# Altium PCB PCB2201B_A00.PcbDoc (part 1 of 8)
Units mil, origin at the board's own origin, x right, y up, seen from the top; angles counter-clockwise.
Board outline 4523.63 x 2358.23 mil, 6 copper layers (Top Layer, Signal Layer 2, Signal Layer 3, Signal Layer 4, Signal Layer 5, Bottom Layer), stack 61.221 mil thick; 383 components, 308 nets, 1386 pads, 1147 vias.
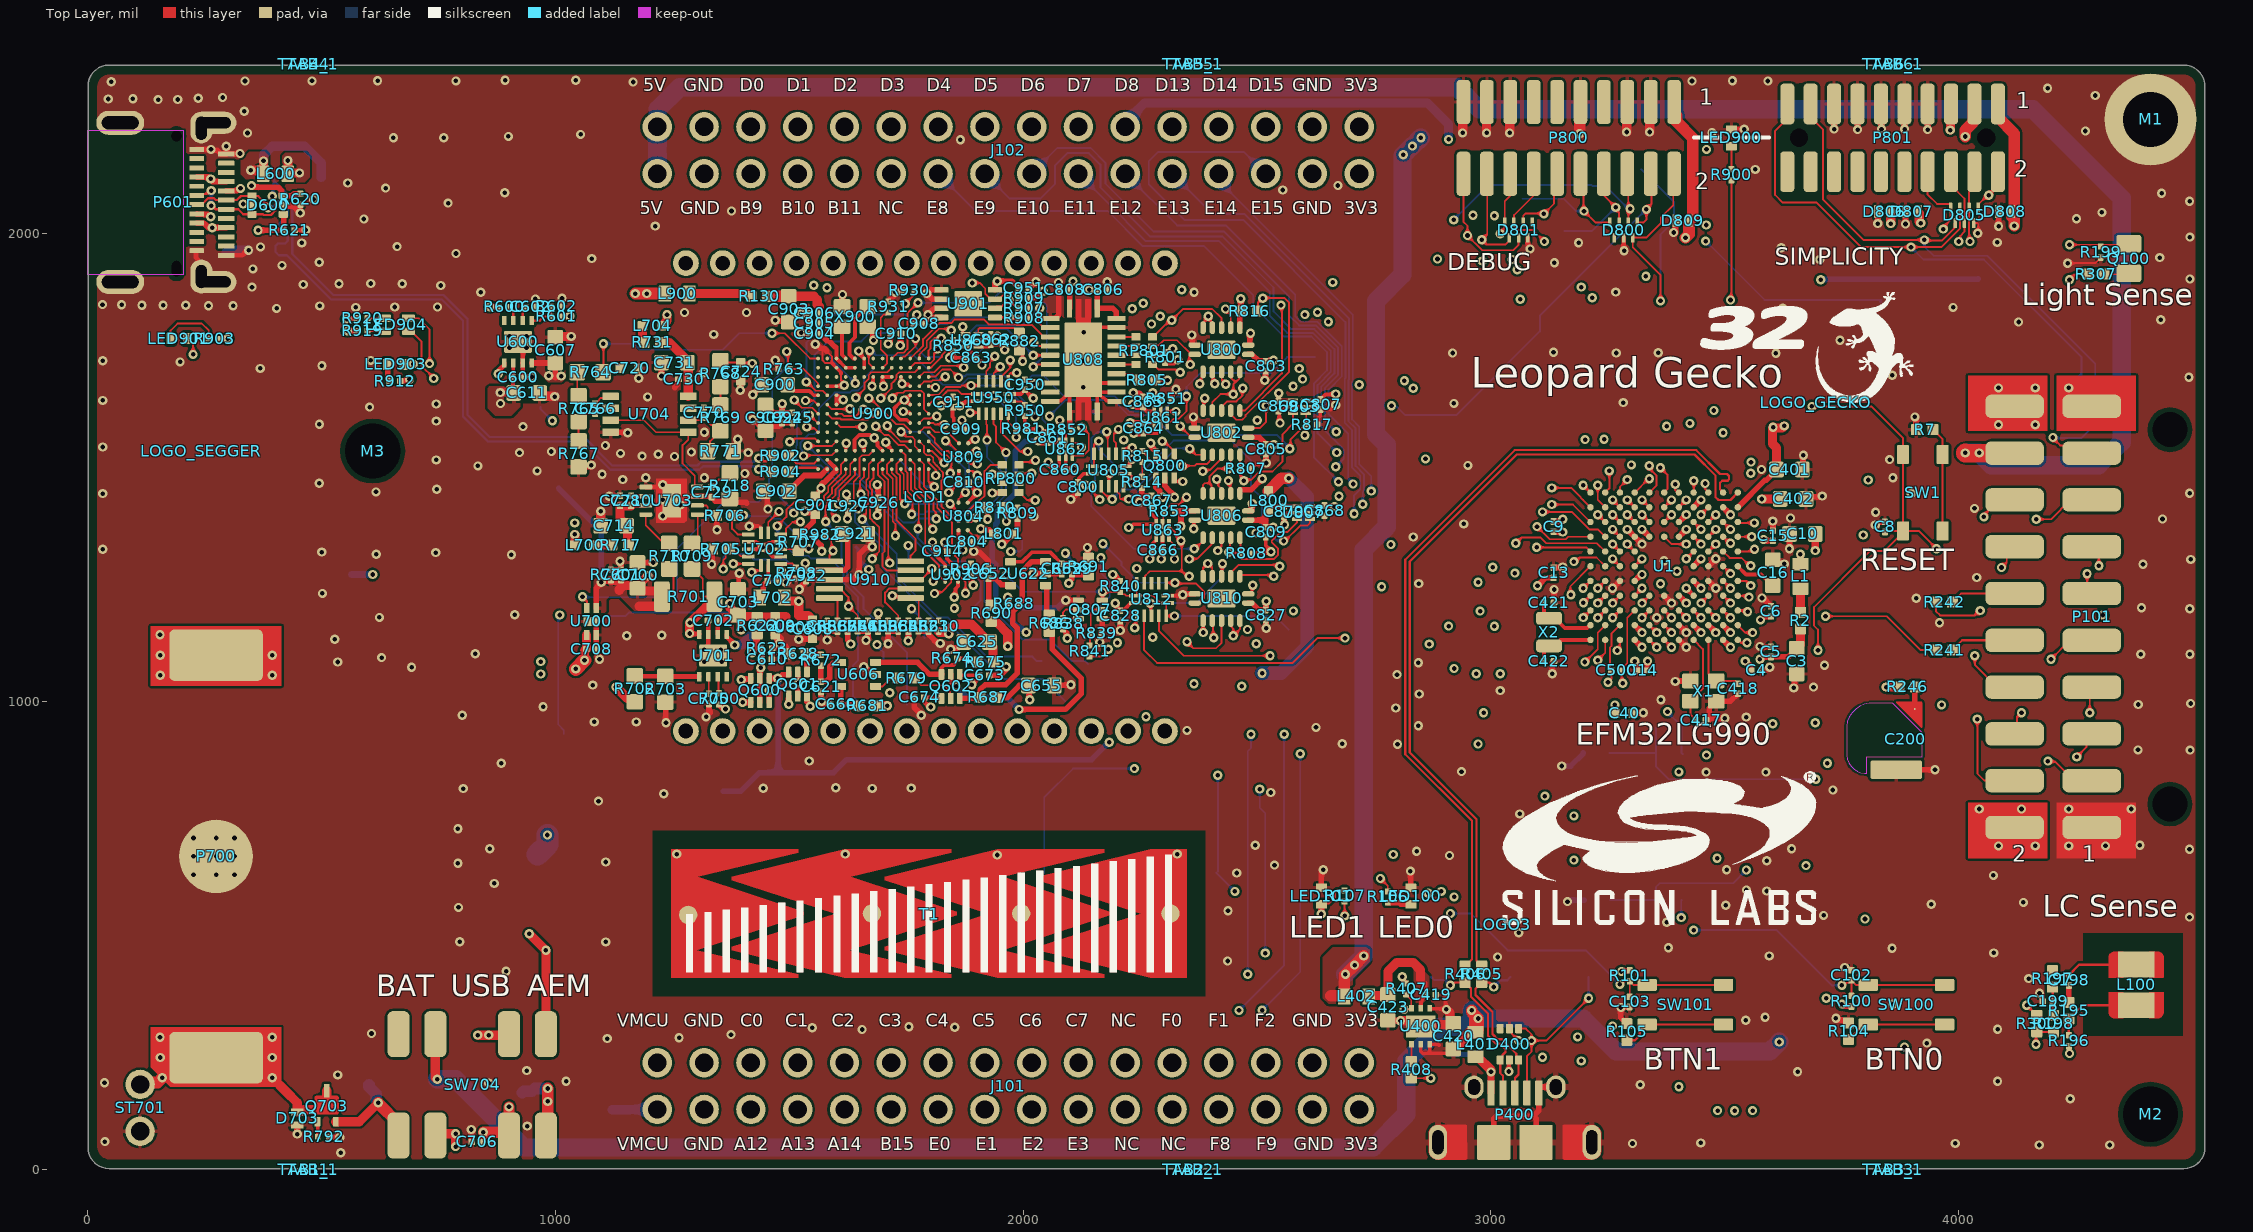
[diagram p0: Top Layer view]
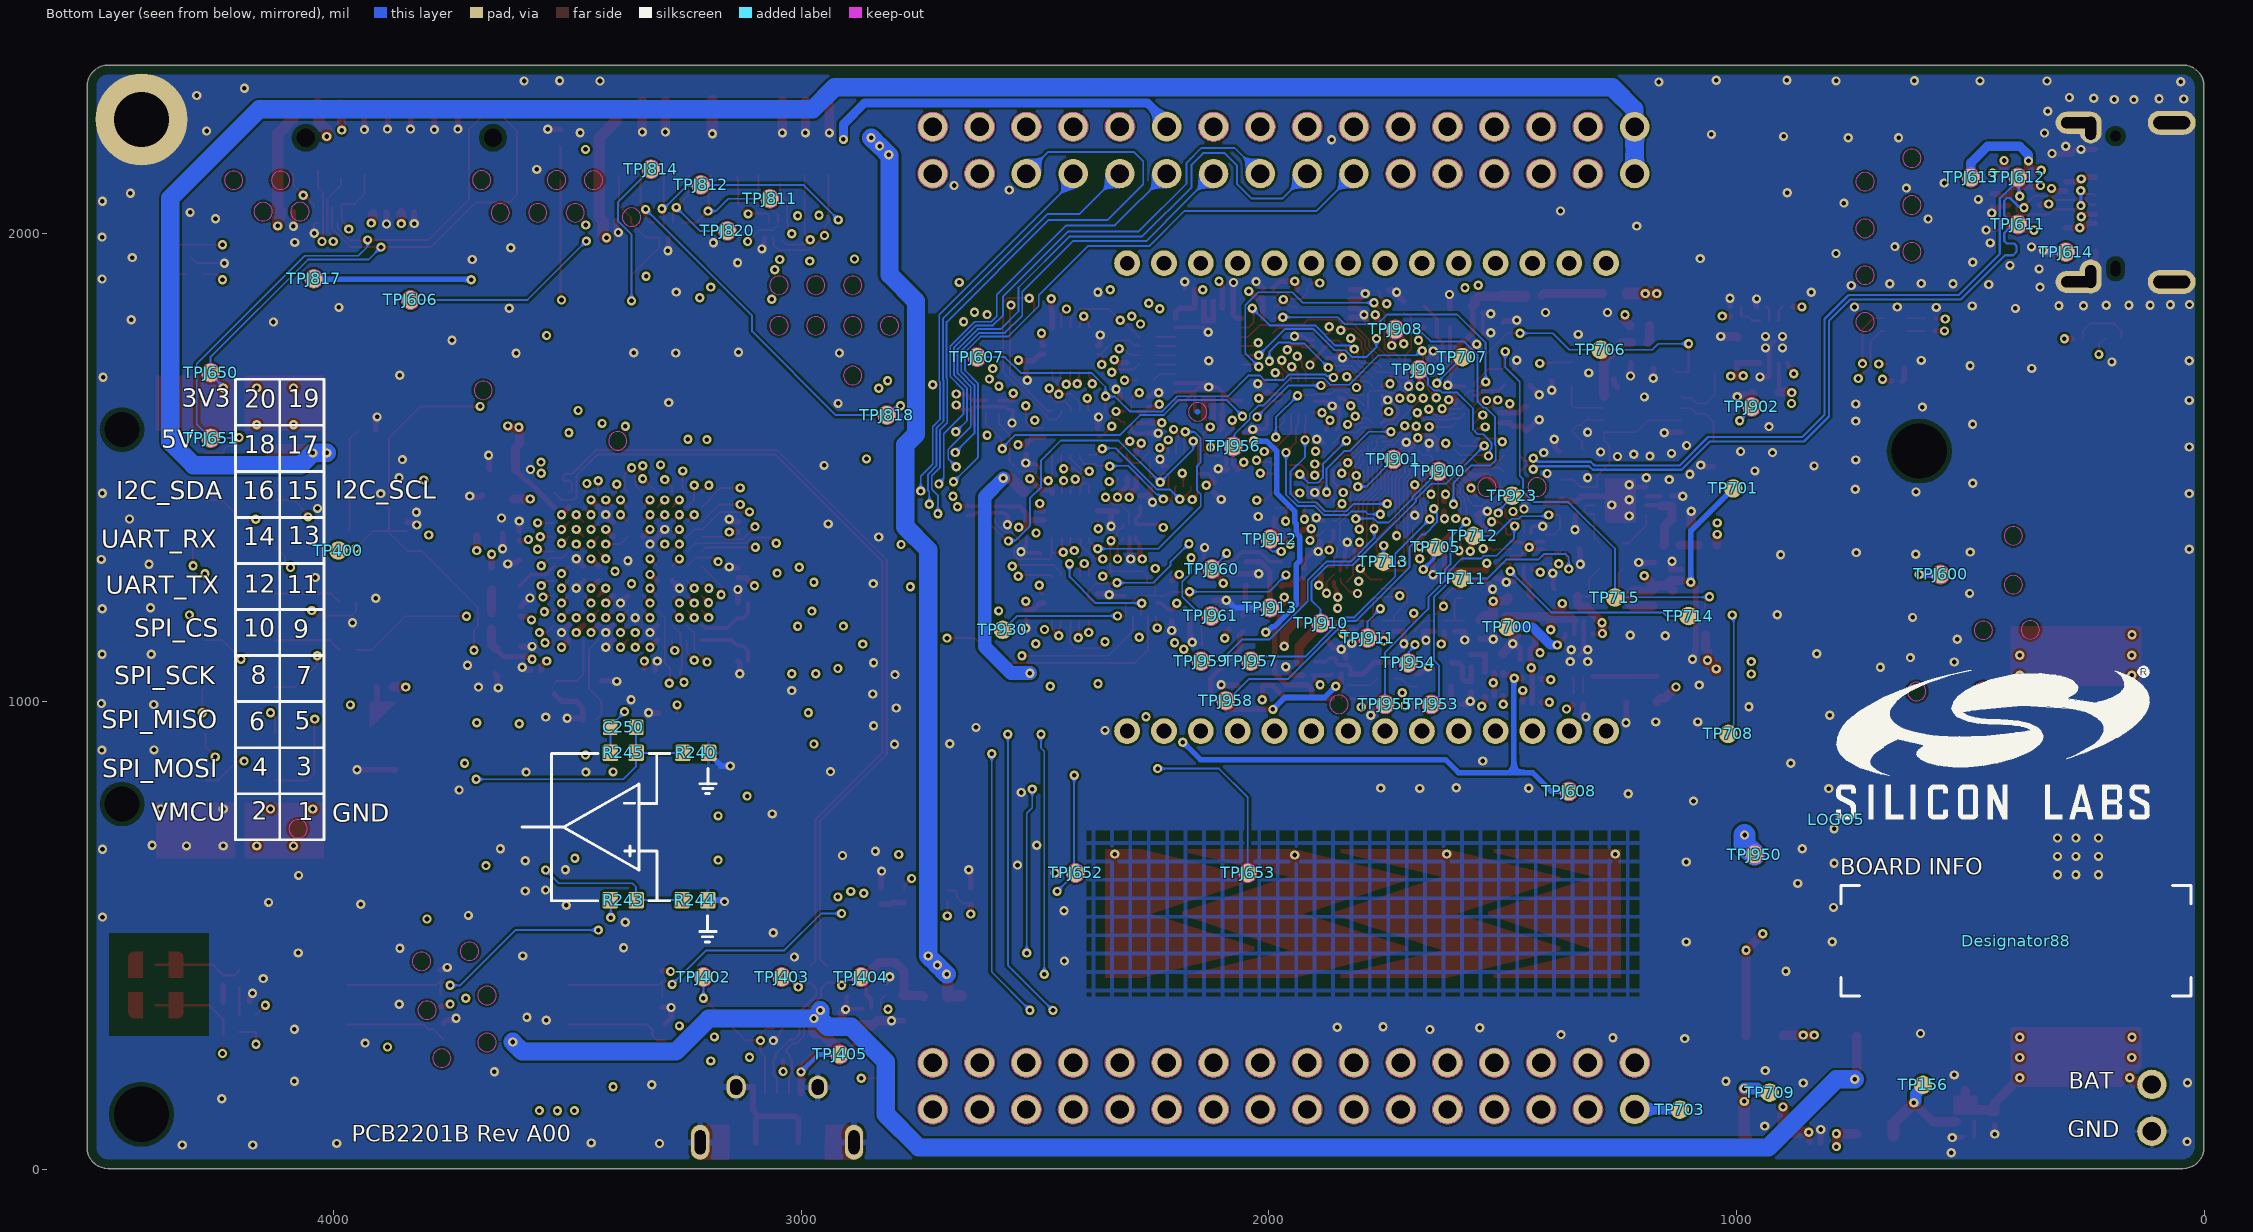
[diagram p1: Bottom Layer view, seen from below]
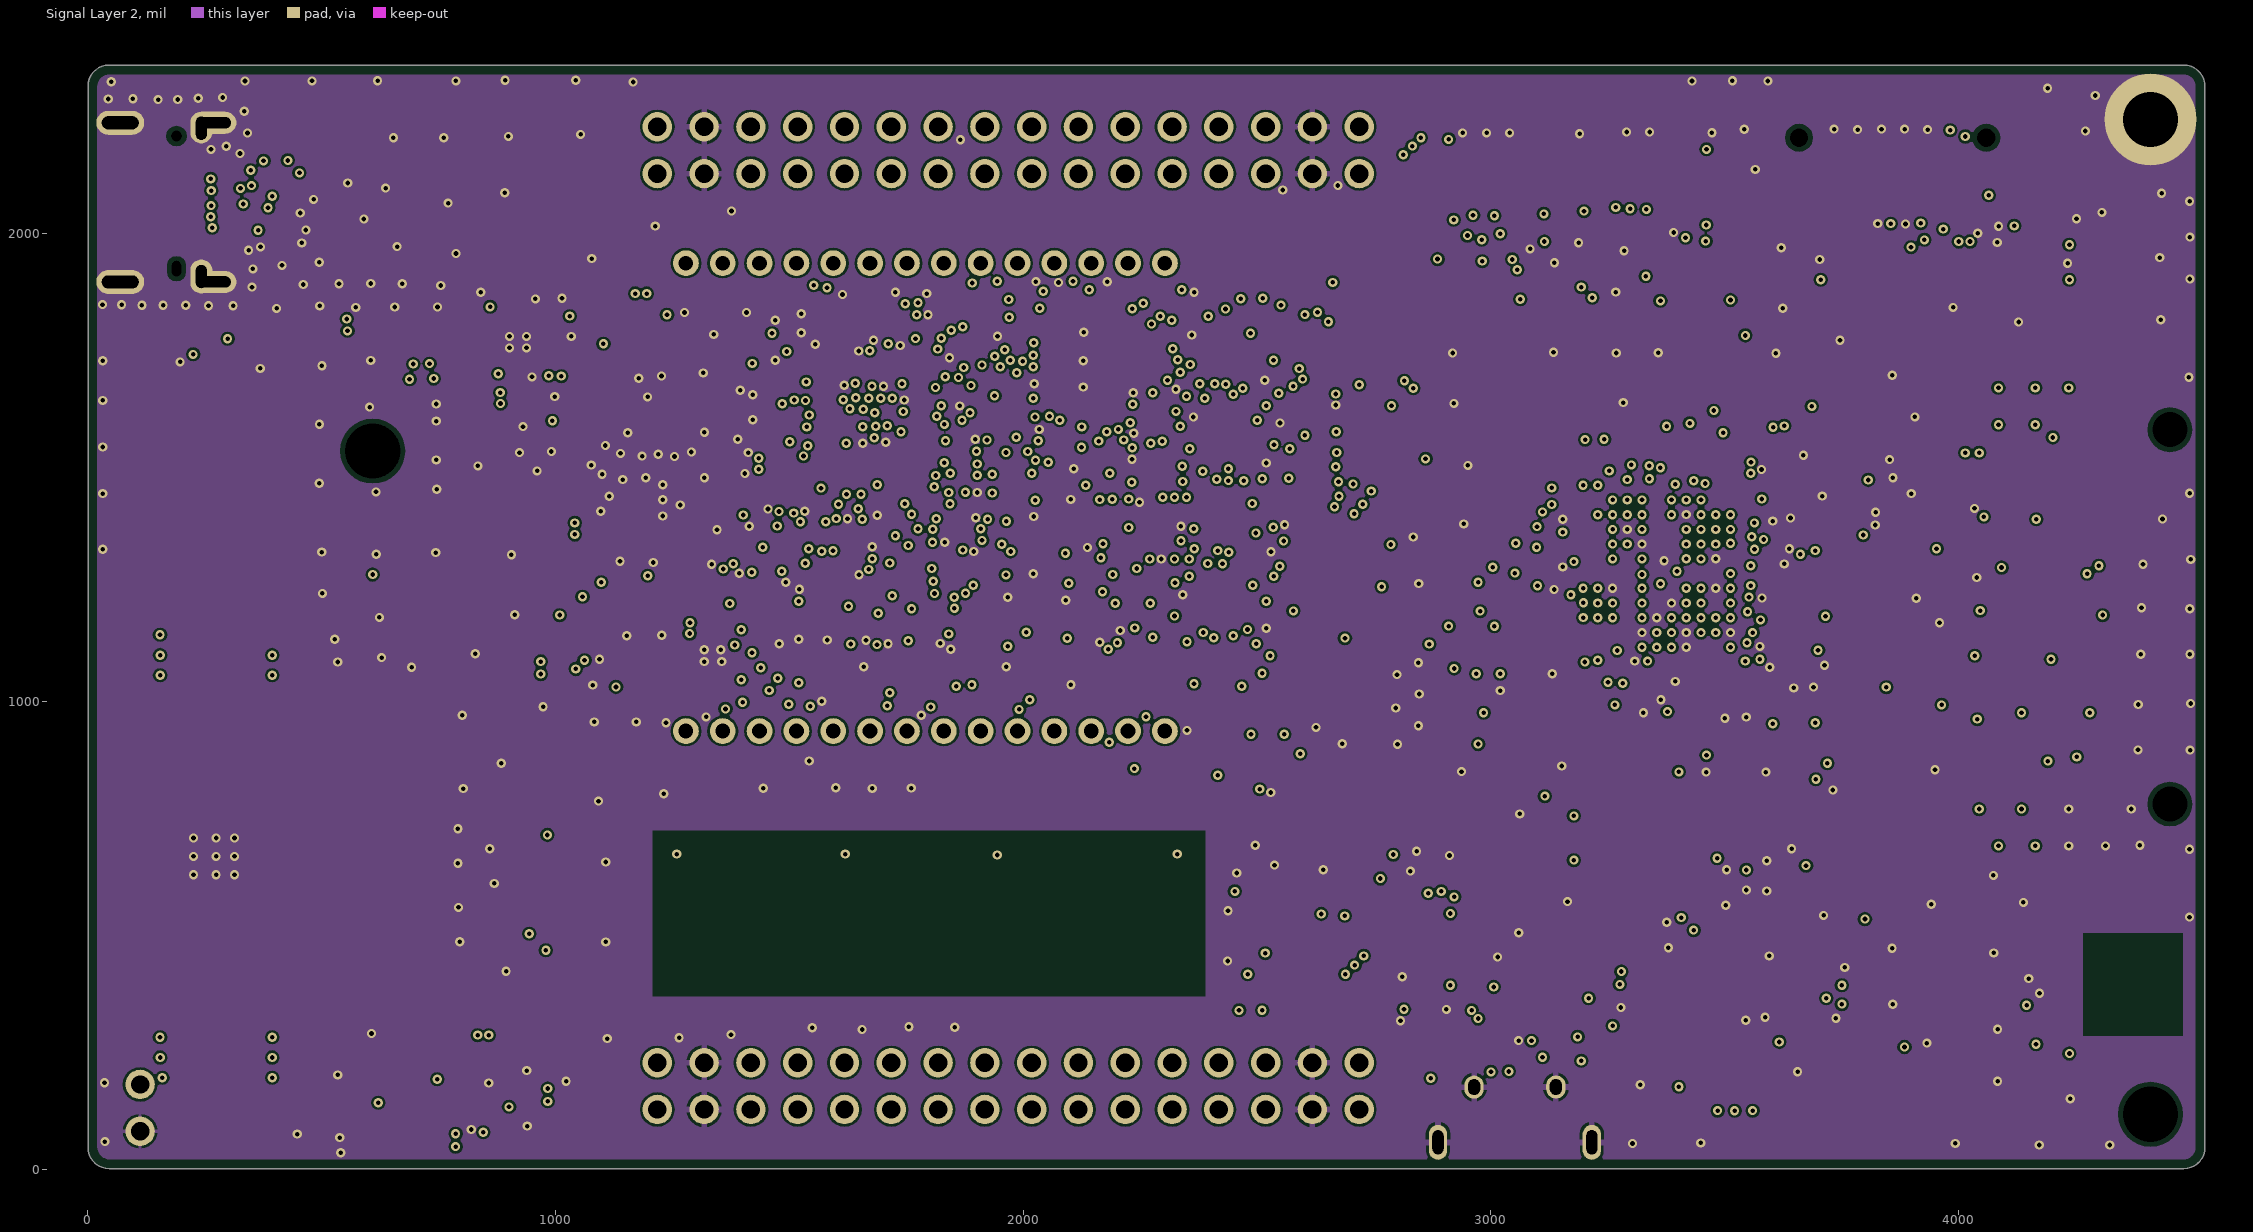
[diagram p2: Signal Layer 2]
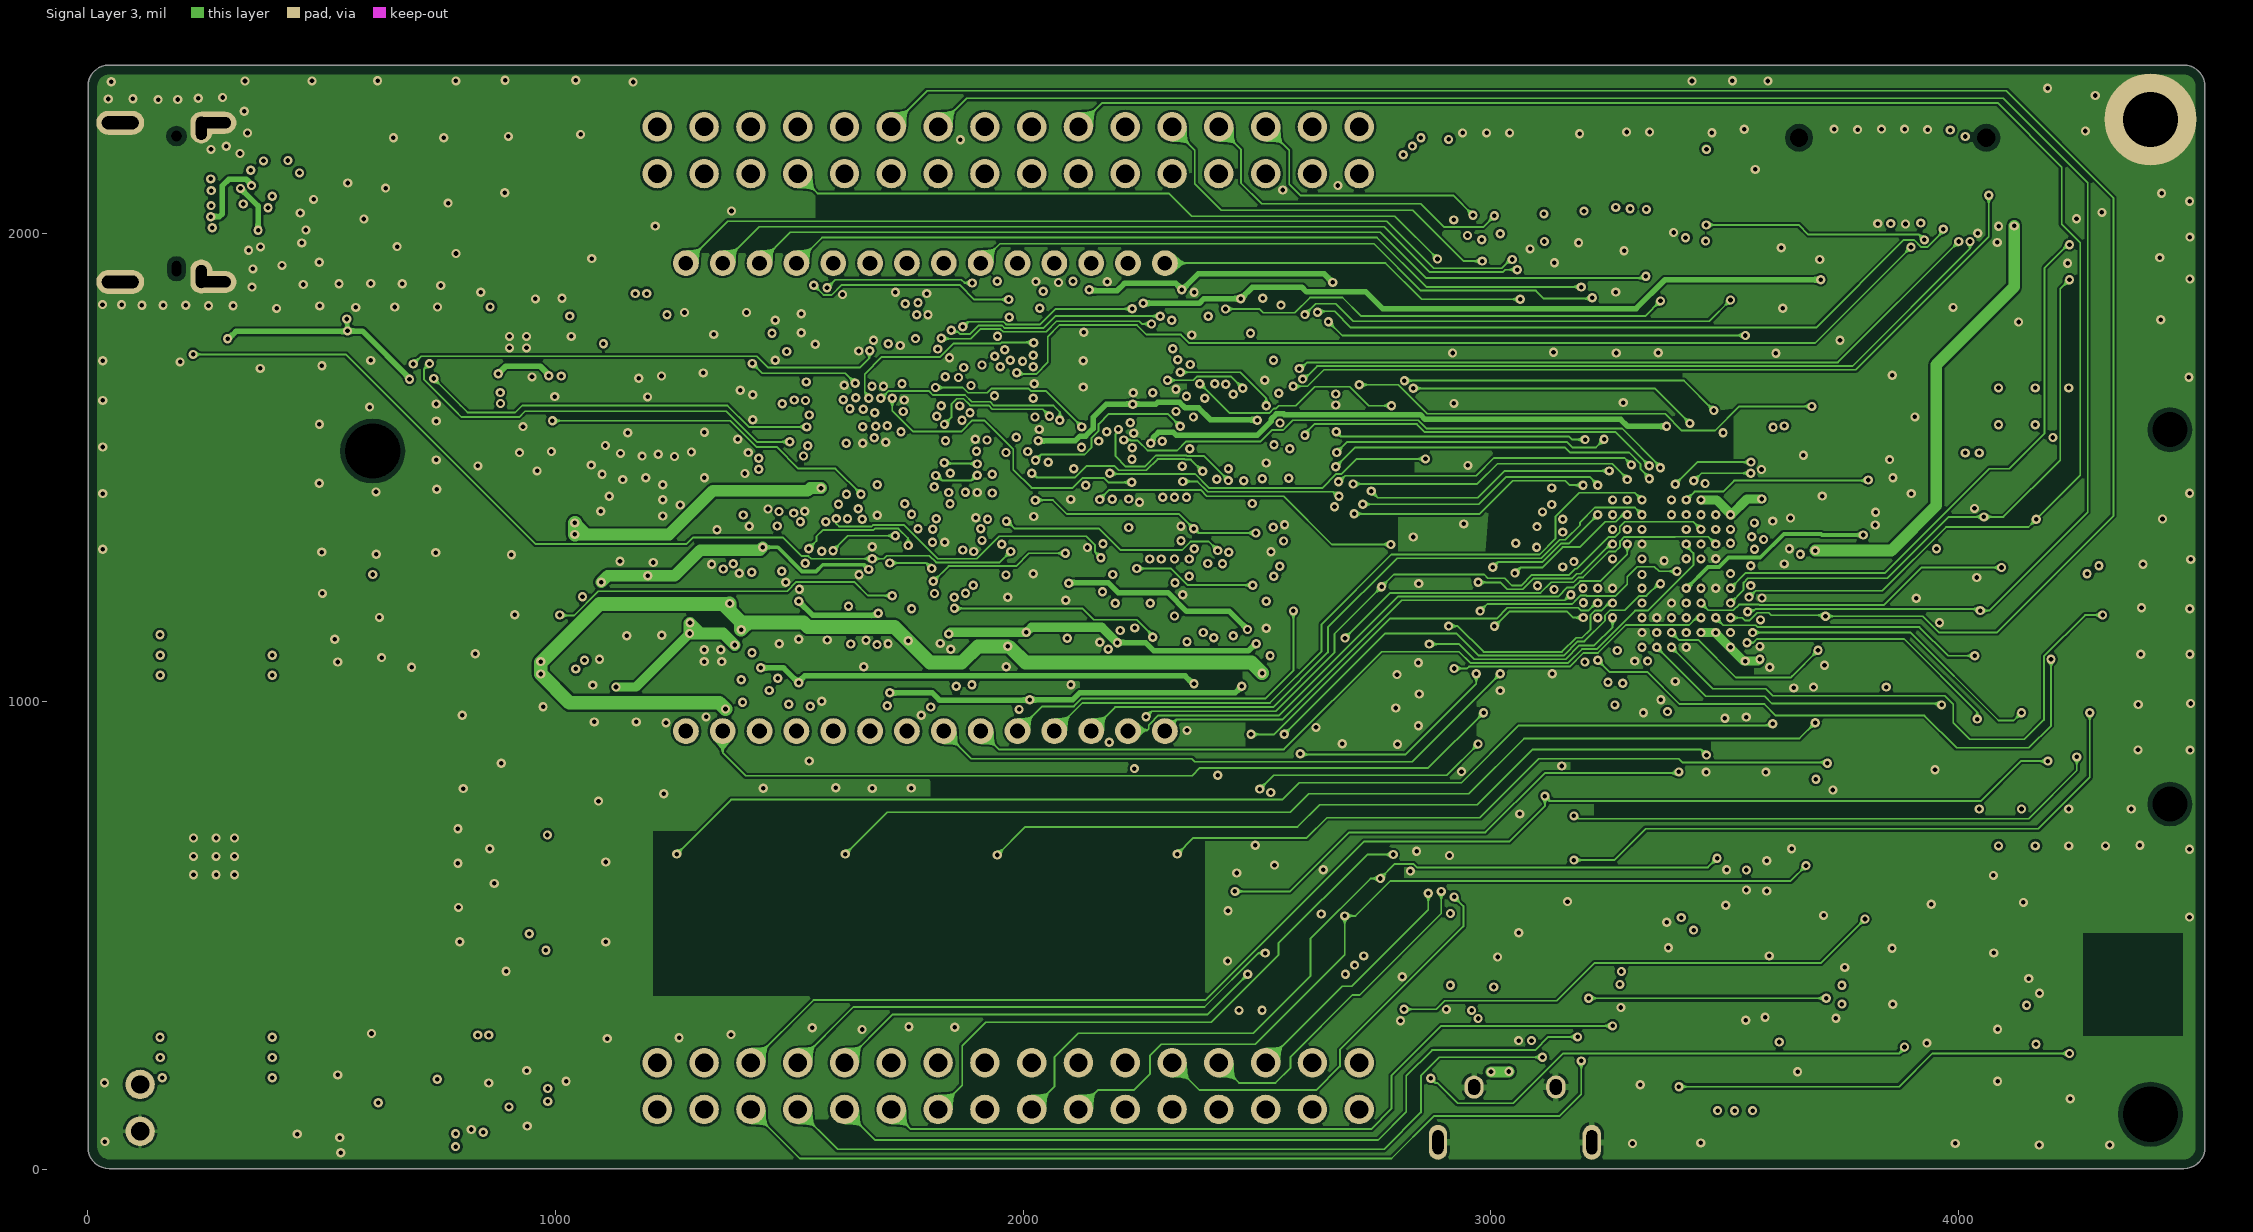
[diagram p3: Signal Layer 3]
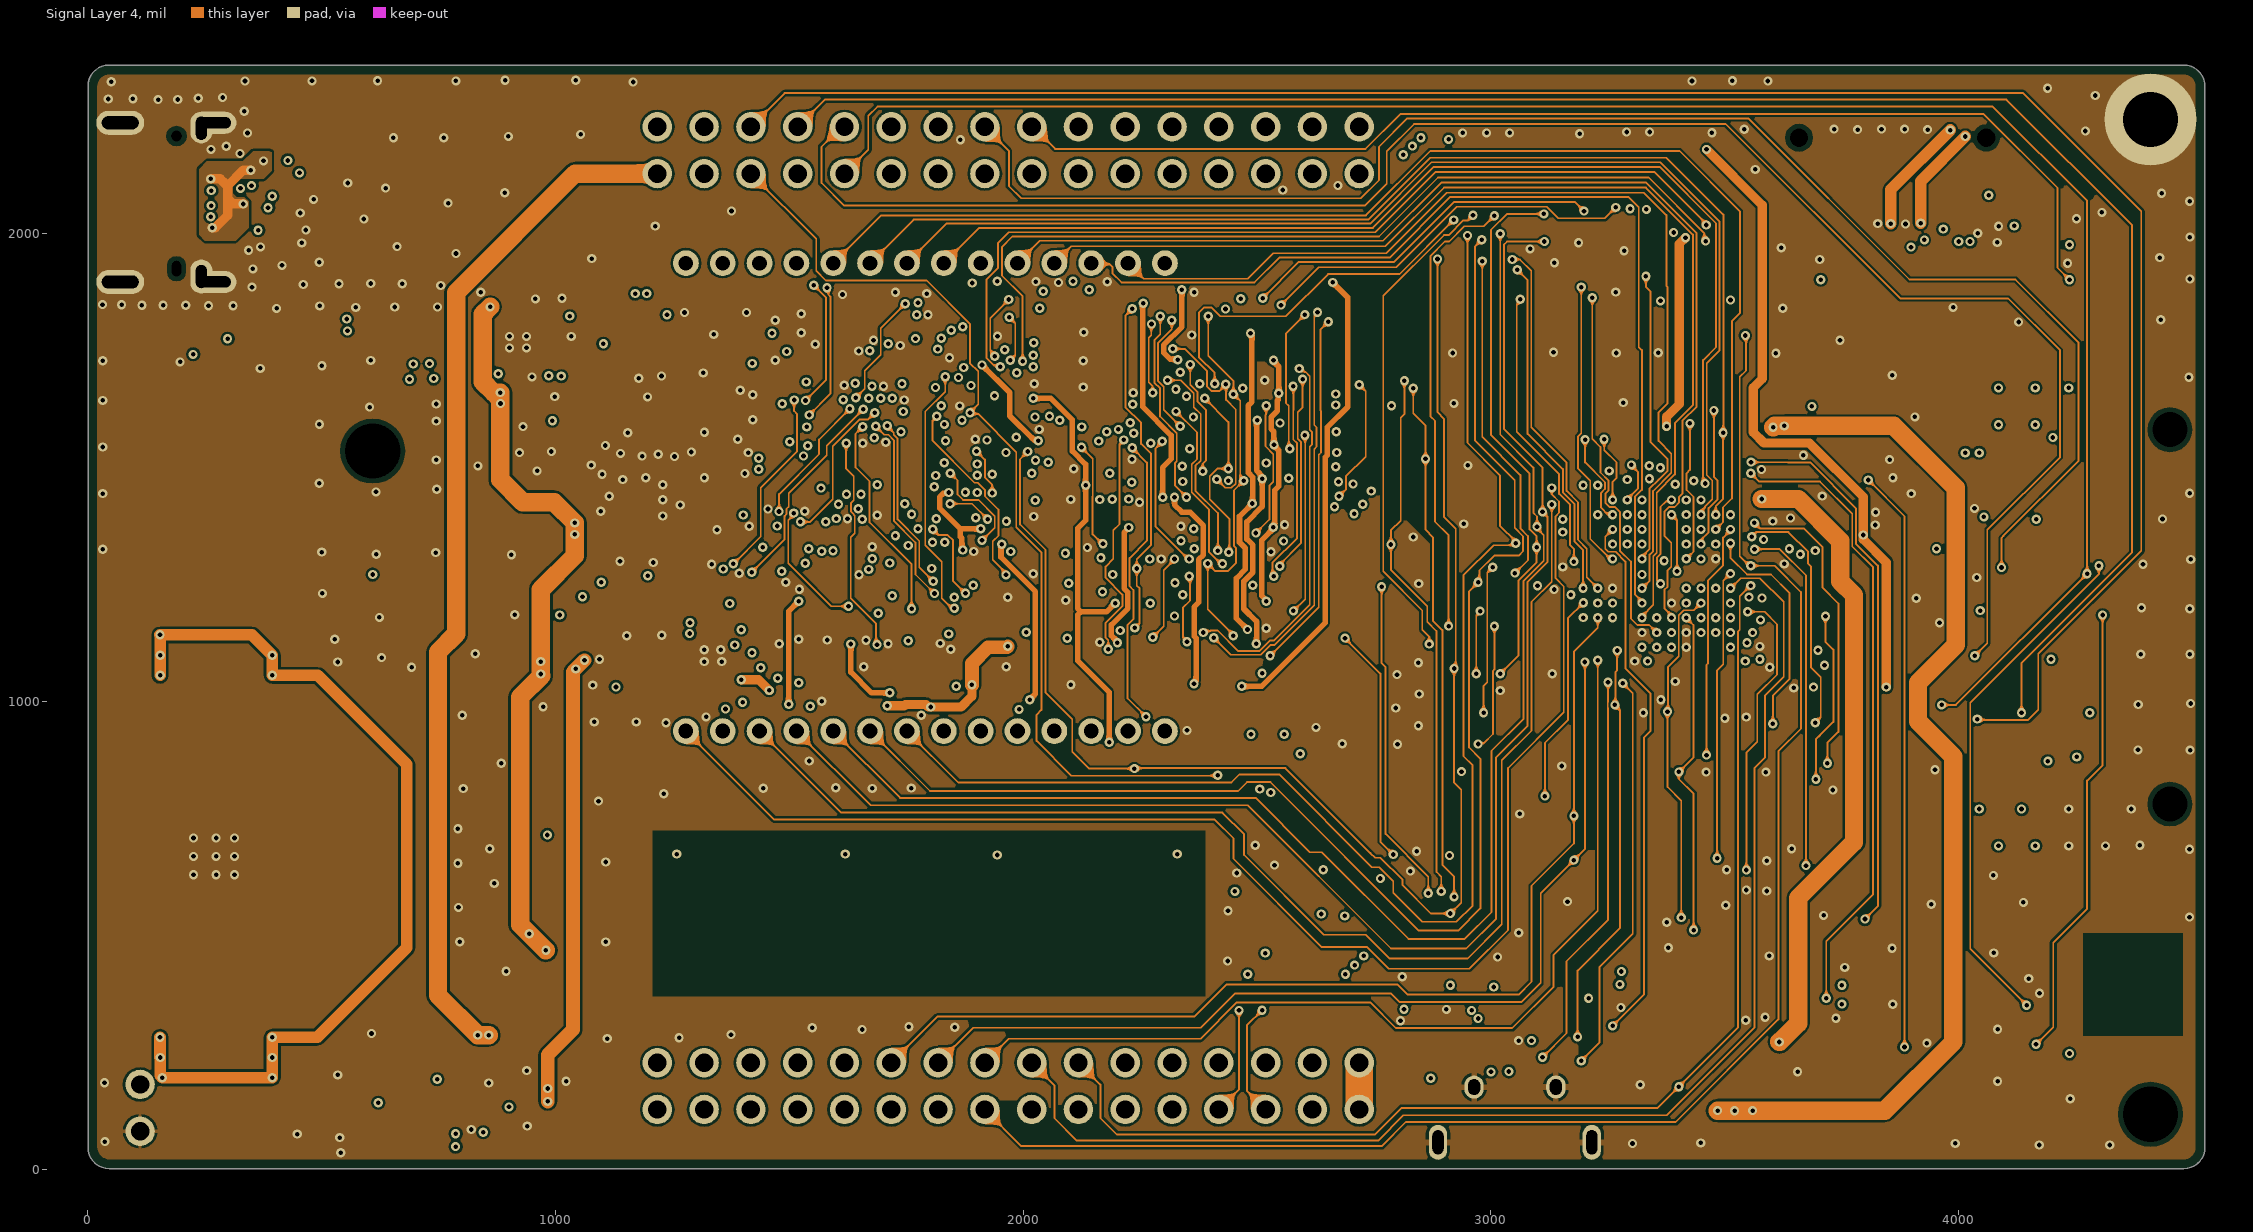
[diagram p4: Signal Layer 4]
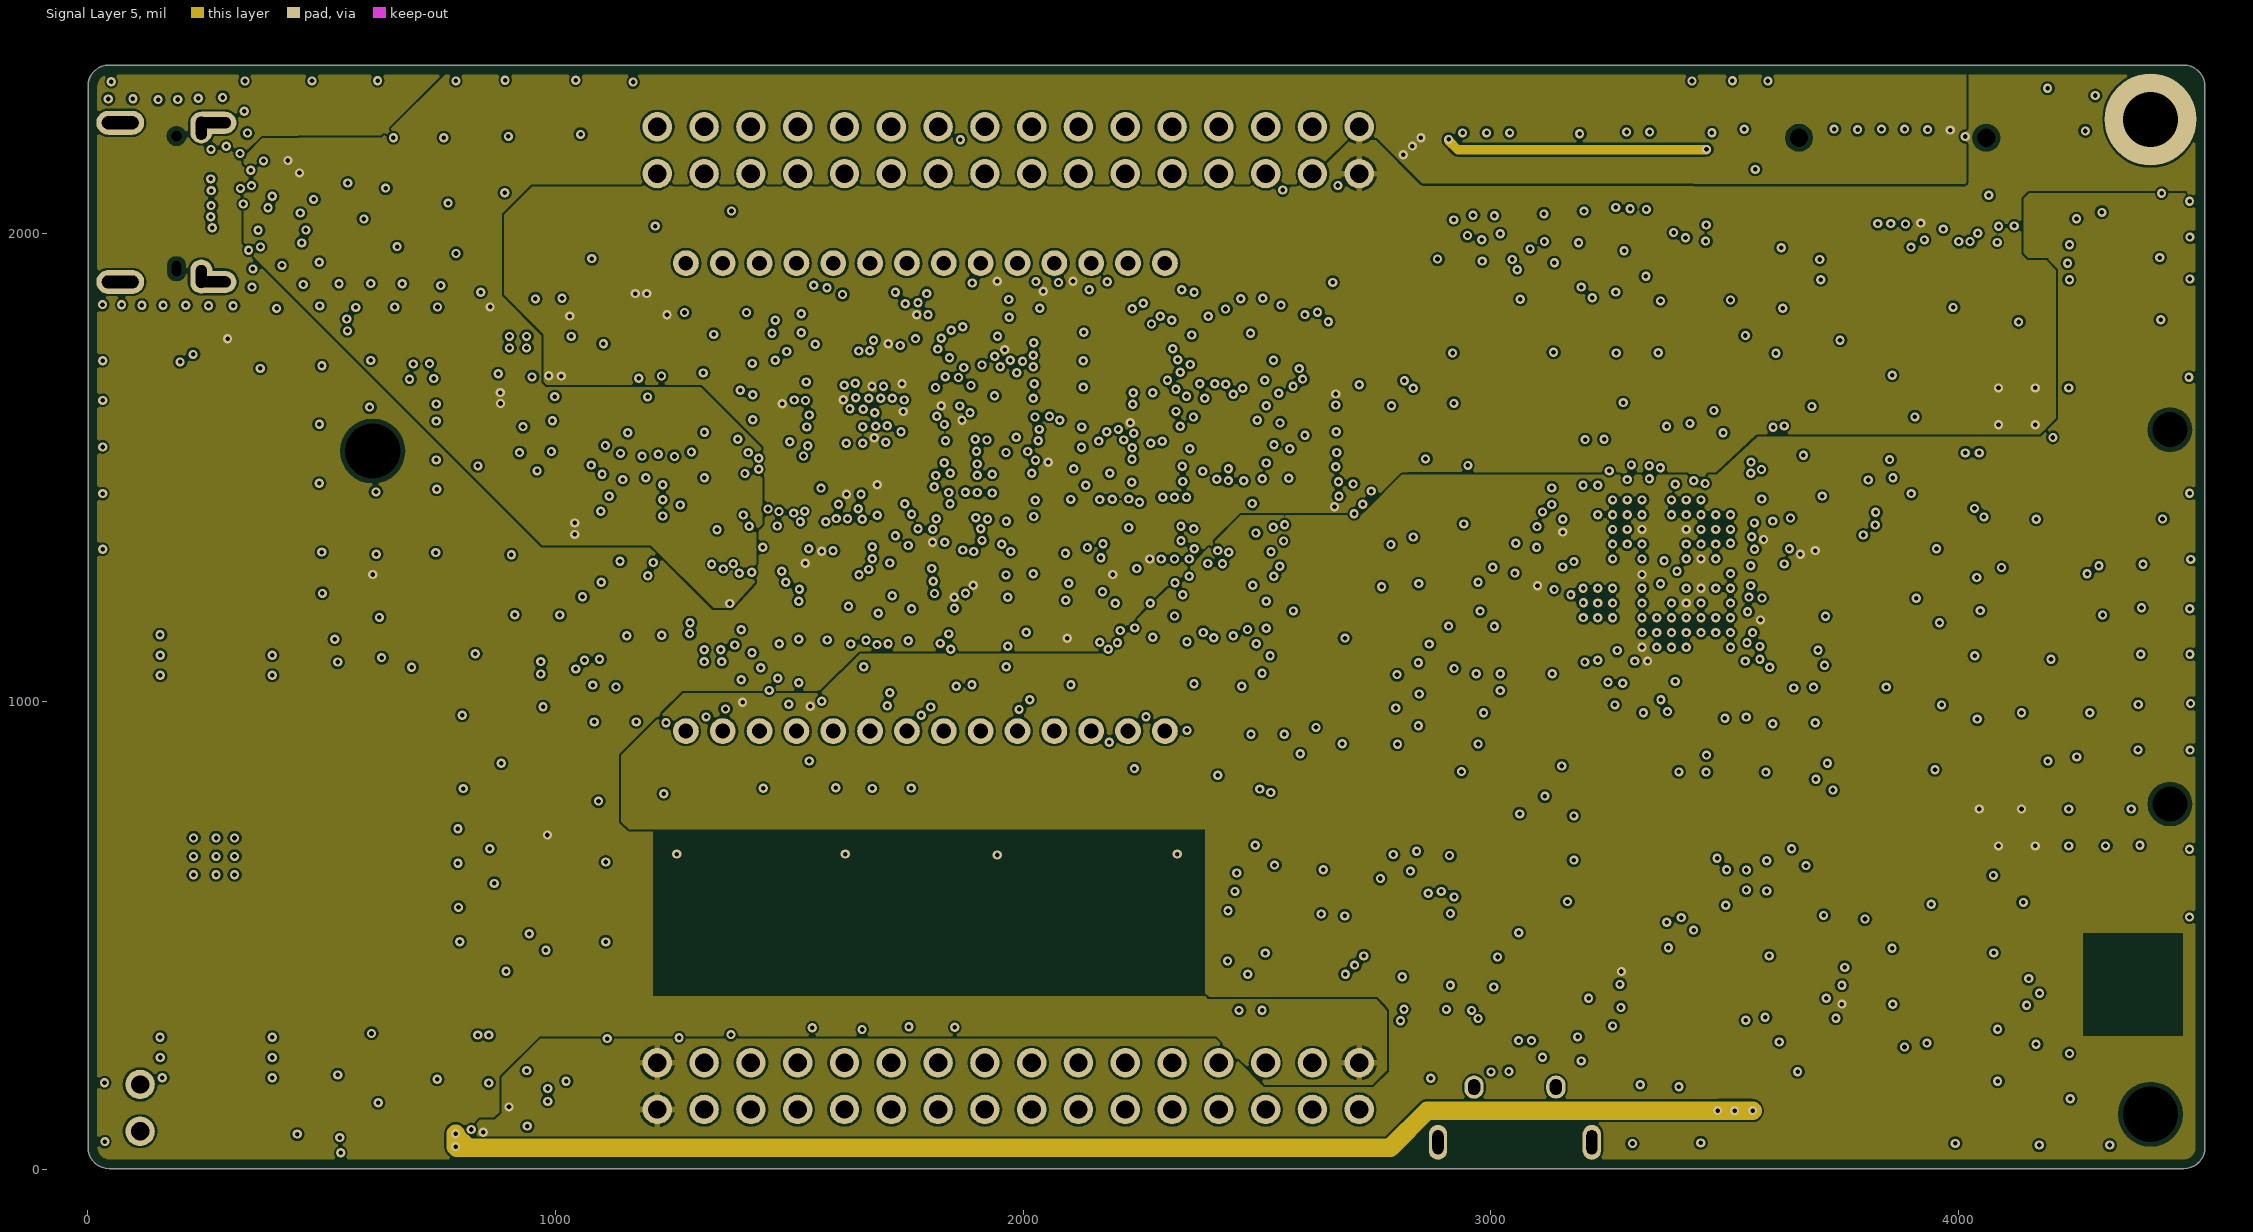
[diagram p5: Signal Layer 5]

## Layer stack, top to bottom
Top Solder: solder mask 1.9685, Solder Resist, Dk 3.5
Top Layer: signal copper 1.378
Dielectric 1: prepreg 3.937, FR-4, Dk 4.2
Signal Layer 2: signal copper 1.378
Dielectric 2: core 18.1102, FR-4, Dk 4.2
Signal Layer 3: signal copper 1.378
Dielectric 3: prepreg 8.8583, FR-4, Dk 4.2
Signal Layer 4: signal copper 1.378
Dielectric 4: core 18.1102, FR-4, Dk 4.2
Signal Layer 5: signal copper 1.378
Dielectric 5: prepreg 3.937, FR-4, Dk 4.2
Bottom Layer: signal copper 1.378
Bottom Solder: solder mask 1.9685, Solder Resist, Dk 3.5

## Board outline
8.03,24.6 4.77,31.78 2.66,39.35 1.98,47.28 1.98,2315.31 2.66,2323.16 4.67,2330.72 8.02,2337.8 12.52,2344.22 17.98,2349.68 24.4,2354.18 31.48,2357.53 39.04,2359.54 46.98,2360.22 4480.22,2360.22 4488.16,2359.54 4495.82,2357.53 4502.91,2354.18 4509.42,2349.68 4514.97,2344.03 4519.48,2337.6 4522.83,2330.42 4524.84,2322.85 4525.62,2315 ccw(c4527.6,2315) 4525.62,2315 4525.62,46.98 4524.94,39.05 4522.83,31.48 4519.57,24.39 4515.08,17.99 4509.53,12.53 4503.1,8.02 4496.01,4.67 4488.55,2.66 4480.62,1.98 47.28,1.98 39.35,2.66 31.78,4.77 24.6,8.03 18.19,12.62 12.62,18.19

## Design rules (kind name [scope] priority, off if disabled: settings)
BoardOutlineClearance [Not InPadClass('Outside_Board')] p1: gap=19.68 ignorepadtopadclearanceinfootprint=FALSE except(10.24: Arc-CutoutEdge Track-CutoutEdge SMDPad-CutoutEdge THPad-CutoutEdge Via-CutoutEdge Fill-CutoutEdge Poly-CutoutEdge Region-CutoutEdge Text-CutoutEdge; 15.75: THPad-OutlineEdge Region-OutlineEdge Region-CavityEdge Region-SplitBarrior Region-SplitContinuation)
Clearance Clearance_NPL [(ObjectKind = 'Pad') And (Layer = 'MultiLayer') And (PadIsPlated = 'False')] p1: gap=9.84 ignorepadtopadclearanceinfootprint=FALSE
Clearance USB [InNetClass('USB')] p2: gap=5.67 ignorepadtopadclearanceinfootprint=FALSE
Clearance "Clearance_ThermalPad to Via" [IsPad and InNet('GND') vs IsVia] p3 off: gap=-39.37 ignorepadtopadclearanceinfootprint=FALSE except(0: Arc-Hole Track-Hole SMDPad-Hole THPad-Hole Via-Hole Fill-Hole Poly-Hole Region-Hole Text-Hole)
Clearance Clearance_Polygon_USB [InPolygon vs InNetClass('USB')] p4: gap=9.84 ignorepadtopadclearanceinfootprint=FALSE except(0: Arc-Hole Track-Hole SMDPad-Hole THPad-Hole Via-Hole Fill-Hole Poly-Hole Region-Hole Text-Hole)
Clearance Clearance_Polygon [InPolygon] p5: gap=4.92 ignorepadtopadclearanceinfootprint=FALSE
Clearance Clearance_Via_Track [IsVia vs IsTrack] p6: gap=3.5 ignorepadtopadclearanceinfootprint=FALSE except(0: Arc-Hole Track-Hole SMDPad-Hole THPad-Hole Via-Hole Fill-Hole Poly-Hole Region-Hole Text-Hole)
Clearance Clearance_Via_Pad [IsVia vs IsPad] p7 off: gap=1 ignorepadtopadclearanceinfootprint=FALSE except(0: Arc-Hole Track-Hole SMDPad-Hole THPad-Hole Via-Hole Fill-Hole Poly-Hole Region-Hole Text-Hole)
Clearance USB_LINE [InNet('DBGMCU_USB_DM') vs InNet('DBGMCU_USB_DP')] p8: gap=4 ignorepadtopadclearanceinfootprint=FALSE
Clearance Pad2PAD [IsPad vs IsPad] p9: gap=3.94 ignorepadtopadclearanceinfootprint=TRUE except(0: Arc-Hole Track-Hole SMDPad-Hole THPad-Hole Via-Hole Fill-Hole Poly-Hole Region-Hole Text-Hole)
Clearance [All] p10: gap=3.94 ignorepadtopadclearanceinfootprint=FALSE
ComponentClearance [All] p1: gap=3.94 collisioncheckmode=3 verticalgap=10 showdistances=TRUE
DiffPairsRouting [InAnyDifferentialPair] p1: maxlimit=4.72 minlimit=4.72 mostfreqgap=4.72 toplayer_minwidth=4.72 toplayer_maxwidth=4.72 toplayer_prefwidth=4.72 midlayer1_minwidth=4.72 midlayer1_maxwidth=4.72 midlayer1_prefwidth=4.72 midlayer2_minwidth=4.72 midlayer2_maxwidth=4.72 midlayer2_prefwidth=4.72 midlayer3_minwidth=4.72 midlayer3_maxwidth=4.72 midlayer3_prefwidth=4.72 midlayer5_minwidth=4.72 midlayer5_maxwidth=4.72 midlayer5_prefwidth=4.72 bottomlayer_minwidth=4.72 bottomlayer_maxwidth=4.72 bottomlayer_prefwidth=4.72 maxuncoupledlength=500
HoleSize [All] p1: absolutevalues=TRUE maxlimit=393.7 minlimit=3.94 maxpercent=80.000 minpercent=20.000
HoleToHoleClearance [InComponent('P601') vs InComponent('P601')] p1: gap=0 allowstackedmicrovias=TRUE
HoleToHoleClearance HoleToHoleClearance_U1toVIA_1 [InComponent ('U1') vs IsVia] p2: gap=0 allowstackedmicrovias=TRUE
HoleToHoleClearance HoleToHoleClearance_general [All] p3: gap=10 allowstackedmicrovias=TRUE
MinimumSolderMaskSliver [All] p1: minsoldermaskwidth=4
ParallelSegment [InNet('MCU_PC11') OR InNet('MCU_PC10') OR InNet('MCU_PC9') OR InNet('MCU_PC8')] p1: limit=472.44 gap=19.29
PolygonConnect [InComponent('J101') or InComponent('J102') vs InNet('GND')and not OnLayer('Signal Layer 2')] p1: connectstyle=NoConnect reliefconductorwidth=10 reliefentries=4 polygonreliefangle="90 Angle" airgapwidth=4.92
PolygonConnect PolygonConnect_TH [InComponent('J101') Or InComponent('J102') Or InComponent('ST1') Or InComponent('P400') Or InComponent('J710')] p2: connectstyle=Relief reliefconductorwidth=13 reliefentries=4 polygonreliefangle="90 Angle" airgapwidth=6
PolygonConnect PolygonConnect_P601 [InComponent('P601')] p3: connectstyle=Direct reliefconductorwidth=13 reliefentries=4 polygonreliefangle="90 Angle" airgapwidth=6
PolygonConnect PolygonConnect_M1 [InComponent('M1')] p4: connectstyle=Direct reliefconductorwidth=13 reliefentries=4 polygonreliefangle="90 Angle" airgapwidth=6
PolygonConnect PolygonConnect_P700 [InComponent('P700')] p5: connectstyle=Direct reliefconductorwidth=13 reliefentries=4 polygonreliefangle="90 Angle" airgapwidth=6
PolygonConnect Polygon_VIA_Connect [IsVia] p6: connectstyle=Direct reliefconductorwidth=10 reliefentries=4 polygonreliefangle="90 Angle" airgapwidth=10
PolygonConnect PolygonConnect_general [All] p7: connectstyle=Relief reliefconductorwidth=7.87 reliefentries=4 polygonreliefangle="90 Angle" airgapwidth=5
RoutingVias [All] p1: holewidth=9.84 width=19.68 viastyle="Through Hole" minholewidth=9.84 minwidth=19.68 maxholewidth=39.37 maxwidth=59.06
ShortCircuit ShortCircuit_General [All] p1: allowed=FALSE
SilkToSilkClearance [All] p1: silktosilkclearance=4
SilkToSolderMaskClearance [IsPad] p1: minsilkscreentomaskgap=4 clearancetoexposedcopper=TRUE
SolderMaskExpansion [All] p1: expansion=2 istentingtop=FALSE
UnRoutedNet [All] p1: checkbadconnections=TRUE
UnpouredPolygon [All] p1: allowunpoured=TRUE allowshelved=TRUE
Width Width_1 [InNetClass('USB')] p1: maxlimit=4.17 minlimit=4.17 preferedwidth=4.17
Width [All] p2: maxlimit=200 minlimit=3.94 preferedwidth=4
20 further rules are at their usual default settings.

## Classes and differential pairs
differential pair class USB: USB1 usb2 usb3
pad class Outside_Board: P400-8 P400-9 P400-10 P400-11
differential pair usb3: +N17457251 -N17457255
differential pair usb2: +EFM_USB_DP -EFM_USB_DM
differential pair USB1: +USB_DP -USB_DM

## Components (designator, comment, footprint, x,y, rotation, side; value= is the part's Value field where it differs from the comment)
C3 "10U" C0603 3653.54,1086.61 r270 top
C4 "10N" C0201 3566.93,1066.93 r0 top
C5 "10N" C0201 3598.43,1106.3 r90 top
C6 "100N" C0201 3598.43,1192.91 r90 top
C8 "100N" C0201 3841.77,1373.27 r90 top
C9 "100N" C0201 3133.86,1374.02 r90 top
C10 "10U" C0603 3665.35,1358.27 r180 top
C13 "100N" C0201 3133.86,1275.59 r90 top
C14 "100N" C0201 3322.83,1066.93 r180 top
C15 "100N" C0201 3602.36,1354.33 r90 top
C16 "1U" C0603 3602.36,1275.59 r90 top
C40 "1U" C0402 3284.45,975.1 r0 top
C102 "1N" C0201 3770.43,415.28 r90 top
C103 "1N" C0201 3296.34,358.23 r270 top
C198 "330P" C0201 4234.96,404.29 r270 top
C199 "100N" C0201 4189.96,359.29 r180 top
C200 "33 mF" BAT_SEIKO_XH311HG 3838.58,917.32 r90 top
C250 "100N" C0603 3379.96,945 r0 bottom
C401 "1U" C0603 3637.8,1496.06 r0 top
C402 "4U7" C0603 3645.67,1433.07 r0 top
C417 "15P" C0201 3448.82,960.63 r0 top
C418 "15P" C0201 3527.56,1027.56 r270 top
C419 "100N" C0201 2871.41,373.41 r0 top
C420 "1U" C0603 2919.33,285.24 r90 top
C421 "18P" C0201 3124.02,1211.61 r0 top
C422 "18P" C0201 3124.02,1086.61 r0 top
C423 "10U" C0603 2779.72,346.54 r270 top
C500 "22N" C0201 3267.72,1066.93 r180 top
C600 "100N" C0201 920.73,1693.13 r0 top
C602 "33N" C0201 947.31,1843.72 r0 top
C607 "10U" C0603 1000.45,1751.2 r90 top
C608 "1U" C0402 1550.2,1154.53 r270 top
C609 "1U" C0402 1470.47,1162.4 r270 top
C610 "1N" C0201 1452.05,1090.63 r0 top
C611 "10U" C0603 939.43,1659.66 r0 top
C621 "100N" C0201 1567.91,1031.5 r270 top
C625 "10U" C0603 1900.63,1127.48 r180 top
C632 "10N" C0201 1776.57,1161.42 r270 top
C635 "10N" C0201 1711.61,1161.42 r270 top
C638 "10N" C0201 1581.69,1161.42 r270 top
C641 "10N" C0201 1646.65,1161.42 r270 top
C652 "100N" C0201 1926.18,1273.62 r90 top
C653 "100N" C0201 2082.68,1283.46 r270 top
C655 "10U" C0603 2039.37,1034.45 r0 top
C660 "100N" C0201 1599.41,994.09 r180 top
C673 "100N" C0201 1917.28,1056.26 r0 top
C674 "100N" C0201 1778.39,1009.13 r180 top
C700 "10U" C0603 1176.18,1269.69 r90 top
C701 "100N" C0201 1140.75,1270.67 r90 top
C702 "100N" C0201 1337.6,1173.23 r180 top
C703 "10U" C0603 1390.75,1212.6 r90 top
C705 "33N" C0201 1328.74,1005.91 r270 top
C706 "100N" C0201 832.68,59.06 r180 top
C707 "100N" C0201 1465.55,1257.87 r0 top
C708 "100N" C0201 1077.76,1112.2 r0 top
C710 "100N" C0201 1162.4,1429.13 r90 top
C714 "10U" C0603 1125,1375.98 r180 top
C720 "1N" C0402 1158.46,1712.6 r0 top
C724 "1N" C0402 1396.65,1704.72 r270 top
C728 "100N" C0201 1138.78,1429.13 r90 top
C729 "2N2" C0201 1334.65,1447.84 r270 top
C730 "100N" C0201 1274.61,1688.98 r180 top
C731 "10U" C0603 1254.92,1724.41 r180 top
C766 "10P" C0201 1085.63,1625.98 r90 top
C770 "10P" C0201 1317.91,1617.13 r90 top
C800 "100N" C0201 2117.13,1457.68 r270 top
C803 "100N" C0201 2518.7,1716.54 r270 top
C804 "100N" C0201 1879.72,1341.85 r0 top
C805 "100N" C0201 2518.7,1539.37 r270 top
C806 "100N" C0201 2170.28,1879.92 r0 top
C807 "100N" C0201 2635.83,1634.84 r270 top
C808 "100N" C0201 2087.6,1879.92 r180 top
C809 "100N" C0201 2518.7,1362.2 r270 top
C810 "100N" C0201 1873.03,1468.5 r0 top
C827 "100N" C0201 2518.7,1185.04 r270 top
C828 "100N" C0201 2207.68,1183.07 r270 top
C860 "100N" C0201 2078.74,1496.06 r0 top
C861 "100N" C0201 2052.17,1563.98 r90 top
C862 "100N" C0201 1931.1,1773.62 r90 top
C863 "100N" C0201 1888.58,1734.8 r180 top
C864 "100N" C0201 2256.89,1584.65 r270 top
C865 "100N" C0201 2256.38,1640.55 r90 top
C866 "100N" C0201 2287.4,1323.82 r0 top
C867 "100N" C0201 2274.8,1429.37 r90 top
C868 "100N" C0201 2644.17,1408.28 r270 top
C869 "100N" C0201 2545.77,1631.7 r270 top
C870 "100N" C0201 2557.66,1406.31 r270 top
C900 "1U" C0603 1469.49,1677.17 r180 top
C901 "1U" C0402 1556.1,1419.29 r270 top
C902 "4U7" C0603 1472.44,1449.8 r180 top
C903 "10U" C0603 1499.02,1838.58 r270 top
C904 "10N" C0201 1554.09,1786.18 r180 top
C905 "10N" C0201 1554.09,1808.86 r180 top
C906 "10N" C0201 1554.09,1830.47 r180 top
C907 "4U7" C0603 1449.8,1606.3 r270 top
C908 "100N" C0201 1777.32,1807.09 r0 top
C909 "100N" C0201 1867.32,1581.73 r180 top
C910 "100N" C0201 1728.43,1786.54 r0 top
C911 "100N" C0201 1850.82,1640.16 r270 top
C914 "100N" C0201 1826.9,1321.44 r0 top
C921 "4U7" C0603 1640.75,1358.27 r0 top
C922 "100N" C0201 1536.42,1268.7 r270 top
C924 "100N" C0201 1485.24,1606.3 r270 top
C925 "100N" C0201 1506.89,1606.3 r270 top
C926 "100N" C0201 1690.95,1425.2 r270 top
C927 "100N" C0201 1625.98,1417.32 r270 top
C950 "10N" C0201 2003.94,1677.17 r90 top
C951 "100N" C0201 2001.97,1883.86 r0 top
D400 "DT1446-04" SOT563_DIODES 3039.37,267.72 r270 top
D600 "DT1446-04" SOT563_DIODES 385.83,2061.02 r180 top
D703 "ESD" X2-DFN1006-2 448.94,109.17 r270 top
D800 "PUSB3AB6" DFN2111-7_M050_1.2X2.1_NXP 3283.46,2007.87 r270 top
D801 "PUSB3AB6" DFN2111-7_M050_1.2X2.1_NXP 3059.06,2007.87 r270 top
D805 "PUSB3AB6" DFN2111-7_M050_1.2X2.1_NXP 4011.81,2039.37 r270 top
D806 "ESD" X2-DFN1006-2 3840.55,2047.24 r180 top
D807 "ESD" X2-DFN1006-2 3899.61,2047.24 r180 top
D808 "ESD" X2-DFN1006-2 4098.43,2047.24 r180 top
D809 "ESD" X2-DFN1006-2 3409.45,2027.56 r180 top
Designator88 "Comment" LABEL_4CORNERS_19.0X6.0 403.54,489.17 r180 bottom
J101 "HEADER_2X16_2.54MM_TH" HDR_M254_RING-2X16 1968.5,178.43 r0 top
J102 "HEADER_2X16_2.54MM_TH" HDR_M254_RING-2X16 1968.5,2178.43 r0 top
L1 "74279266" COIL_WURTH_CBF_0603 3661.42,1267.72 r270 top
L100 "390uH" COIL_BOURNS_SDR0302 4378.83,394.69 r270 top
L401 "742792662" COIL_WURTH_CBF_0603 2967.17,267.52 r90 top
L402 "742792662" COIL_WURTH_CBF_0603 2712.6,370.08 r0 top
L600 "742792662" COIL_WURTH_CBF_0603 402.56,2127.95 r0 top
L700 "742792796" COIL_0402 1062.99,1334.65 r0 top
L702 "74279266" COIL_WURTH_CBF_0603 1463.58,1222.44 r180 top
L704 "742792796" COIL_0402 1207.68,1803.15 r180 top
L800 "742792796" COIL_0402 2524.61,1429.13 r270 top
L801 "742792796" COIL_0402 1958.66,1358.27 r180 top
L900 "74279266" COIL_WURTH_CBF_0603 1260.83,1872.05 r0 top
LCD1 "CL010-1087-04" LCD_TRI-T_CL010-1087-03 1791.34,1437.01 r0 top
LED100 "YELLOW" LED_0402_CAT2 2828.74,584.48 r90 top
LED101 "YELLOW" LED_0402_CAT2 2637.8,584.48 r90 top
LED900 "Yellow" LED_0402_CAT2 3513.78,2204.72 r90 top
LED901 "Blue" LED_0402_CAT2 196.06,1775.98 r0 top
LED903 "RED" LED_0402 659.02,1720.87 r180 top
LED904 "LED_G_R" LED_AVAGO_HSMF-C165-4 660.98,1805.51 r0 top
LOGO3 "Comment" LOGO_SILABS_W18.0 3025.59,523.62 r0 top
LOGO5 "Comment" LOGO_SILABS_W18.0 787.4,748.03 r180 bottom
LOGO_GECKO "Comment" LOGO_GECKO_H6.0 3693.54,1638.43 r0 top
LOGO_SEGGER "Comment" LOGO_SEGGER_10.0X5.0_SM 244.09,1535.43 r0 top
M1 "HOLE_PTH_3MM" HOLE_3.0_5.0_PL 4409.45,2244.09 r0 top
M2 "HOLE_TH_3MM" HOLE_3.0_NPL 4409.45,118.11 r0 top locked
M3 "Comment" HOLE_3.0_NPL 610.24,1535.43 r0 top
P101 "HEADER_2X10_2.54MM_TH" WCON_1125B-1210_HOR_PEG-2X10 4450.91,781.1 r90 top
P400 "USB_Micro_AB" MOL_47589-0001_MICRO_USB-AB 3051.18,0.98 r0 top
P601 "FCI_10137065_USB-C_RCPT" FCI_10137065_USB-C_RCPT 190.94,2066.93 r270 top
P700 "CR2032" BAT_HOLD_MPD_BK-912_CR2032 275.59,669.29 r90 top
P800 "HEADER_DEBUG_ETM" WCON_3132_HDR_M127_SMD-2X10 3166.34,2204.72 r180 top
P801 "HEADER_2X10_1.27MM_SMD" HDR_SULLINS_M127_PEG-2X10 4058.27,2204.72 r180 top
Q100 "TEMT6200FX01" TEMT6200FX01_GEN_0805 4363.19,1946.85 r90 top
Q600 "BSS84" SOT563 1437.52,1024.02 r90 top
Q601 "DMN5L06VK" SOT563 1518.7,1037.4 r90 top
Q602 "BSS84" SOT563 1845.47,1032.48 r90 top
Q703 "DMG3415" X2-DFN2015-3_DIODES 511.81,137.8 r90 top
Q800 "DMN5L06VK" SOT563 2303.15,1503.94 r270 top
Q807 "DMN5L06VK" SOT563 2143.7,1196.85 r180 top
R2 "1R" R0402 3661.42,1173.23 r270 top
R7 "100R" R0402 3926.64,1581.16 r0 top
R100 "1M" R0201 3770.43,359.65 r270 top
R101 "1M" R0201 3296.69,414.21 r90 top
R104 "100R" R0402 3764.06,295.51 r90 top
R105 "100R" R0402 3290.32,294.09 r90 top
R106 "2K05" R0201 2779.53,582.68 r90 top
R107 "2K05" R0201 2687.01,584.65 r270 top
R130 "1R" R0402 1436.02,1866.14 r0 top
R195 "0R" R0402 4235.13,339.57 r90 top
R196 "1K5" R0201 4234.96,275.32 r90 top
R197 "0R" R0402 4199.88,407.48 r90 top
R198 "0R" R0402 4201.66,312.01 r90 top
R199 "22K" R0201 4303.15,1960.63 r270 top
R240 "10K" R0603 3225.12,890.43 r0 bottom
R241 "0R" R0402 3968.5,1110.24 r0 top
R242 "0R" R0402 3968.5,1212.6 r0 top
R243 "10K" R0603 3379.96,575.79 r0 bottom
R244 "10K" R0603 3226.89,575.79 r0 bottom
R245 "10K" R0603 3379.96,890.43 r0 bottom
R246 "100R" R0402 3889.76,1031.5 r0 top
R300 "0R" R0402 4166.34,312.01 r90 top
R307 "0R" R0402 4292.76,1913.39 r0 top
R405 "15R" R0402 2980.31,417.32 r90 top
R406 "15R" R0402 2944.88,417.32 r90 top
R407 "1M" R0201 2818.66,385.94 r270 top
R408 "0R" R0402 2829.68,213.31 r90 top
R600 "10K" R0201 891.2,1843.72 r180 top
R601 "180K" R0201 1002.42,1823.05 r0 top
R602 "110K" R0201 1002.42,1844.7 r180 top
R620 "5K1" R0201 455.71,2073.82 r90 top
R621 "5K1" R0201 431.9,2007.35 r180 top
R622 "47R" R0402 1432.09,1162.4 r90 top
R623 "10K" R0201 1452.05,1113.66 r180 top
R628 "1M" R0402 1518.7,1102.36 r180 top
R629 "1K" R0201 2104.33,1283.46 r270 top
R630 "4K7" R0201 1819.88,1161.42 r270 top
R631 "10K" R0201 1798.23,1161.42 r90 top
R633 "47K" R0201 1754.92,1161.42 r270 top
R634 "47K" R0201 1733.27,1161.42 r90 top
R636 "47K" R0201 1625,1161.42 r270 top
R637 "47K" R0201 1603.35,1161.42 r90 top
R639 "47K" R0201 1689.96,1161.42 r90 top
R640 "47K" R0201 1668.31,1161.42 r90 top
R672 "1K" R0201 1567.91,1088.58 r90 top
R674 "4K7" R0201 1847.44,1092.52 r180 top
R675 "3R3" R0402 1919.76,1084.61 r0 top
R679 "0R" R0402 1750,1050.2 r0 top
R681 "33R" R0402 1667.32,991.14 r0 top
R686 "0R" R0402 2056.1,1167.32 r270 top
R687 "3R3" R0402 1925.2,1008.86 r0 top
R688 "4K7" R0201 1980.32,1209.65 r180 top
R690 "33R" R0402 1932.09,1188.98 r270 top
R691 "1M" R0402 2139.8,1288.7 r90 top
R700 "10K" R0201 1350.39,1005.91 r270 top
R701 "4R7" R1206 1284.45,1224.41 r180 top
R702 "180K" R0603 1170.26,1027.38 r270 top
R703 "110K" R0603 1235.55,1026.5 r90 top
R705 "267R" R0402 1354.45,1326.17 r0 top
R706 "10K2" R0402 1362.33,1397.76 r0 top
R707 "24K9" R0402 1519.7,1340.63 r270 top
R708 "1M" R0201 1515.07,1274.78 r90 top
R709 "1K8" R0603 1292.6,1311.02 r270 top
R710 "1K8" R0603 1243.7,1311.02 r270 top
R717 "10R" R0402 1138.78,1334.65 r0 top
R718 "12K" R0603 1373.74,1461.61 r90 top
R731 "1R" R0402 1207.68,1767.72 r180 top
R760 "330K" R0201 1119.09,1270.67 r270 top
R763 "100K" R0201 1489.17,1710.63 r0 top
R764 "90R9" R0603 1074.8,1703.74 r0 top
R765 "51K" R0603 1050.2,1625.98 r90 top
R767 "160R" R0603 1050.2,1529.53 r90 top
R768 "90R9" R0603 1353.35,1700.79 r90 top
R769 "51K" R0603 1353.35,1606.3 r90 top
R771 "51K" R0603 1353.35,1535.43 r180 top
R792 "1K" R0201 505.28,70.16 r180 top
R801 "47K" R0201 2303.69,1735.53 r270 top
R805 "33R" R0402 2264.76,1687.01 r0 top
R807 "100K" R0201 2476.38,1498.03 r0 top
R808 "100K" R0201 2477.13,1316.69 r0 top
R809 "100K" R0201 1988.19,1402.56 r270 top
R810 "33R" R0402 1939.96,1414.37 r0 top
R814 "100K" R0201 2254.09,1468.52 r90 top
R815 "1K" R0201 2254.95,1523.88 r270 top
R816 "100K" R0402 2483.27,1834.65 r180 top
R817 "100K" R0201 2616.94,1591.98 r180 top
R838 "100K" R0201 2085.63,1166.34 r270 top
R839 "10M" R0201 2156.5,1146.65 r180 top
R840 "100K" R0201 2207.68,1246.06 r90 top
R841 "1K" R0201 2142.15,1108.08 r270 top
R850 "100K" R0201 1850.67,1760.32 r90 top
R851 "100K" R0201 2305.98,1646.93 r180 top
R852 "100K" R0201 2093.5,1580.71 r180 top
R853 "100K" R0201 2312.99,1406.5 r180 top
R882 "220R" R0402 1992.13,1769.69 r270 top
R900 "2K05" R0201 3513.78,2125.98 r90 top
R902 "33R" R0402 1481.3,1525.59 r0 top
R903 "5K76" R0201 271.65,1775.59 r180 top
R904 "33R" R0402 1481.3,1491.14 r0 top
R906 "10K" R0201 1888.75,1283.38 r270 top
R907 "4K7" R0201 2001.97,1840.55 r180 top
R908 "4K7" R0201 2001.97,1818.9 r180 top
R909 "10K" R0201 2001.97,1862.2 r180 top
R912 "2K15" R0201 657.48,1685.04 r180 top
R919 "1K" R0201 587.48,1792.56 r0 top
R920 "2K37" R0201 587.48,1819.49 r0 top
R930 "1K" R0201 1756.42,1878.66 r180 top
R931 "1K" R0201 1711.98,1843.34 r90 top
R950 "100K" R0201 2003.94,1622.05 r270 top
R981 "100K" R0201 1997.05,1582.68 r0 top
R982 "10K" R0201 1565.79,1356.38 r0 top
RP800 "33R" RES_MNR04-8 1973.43,1476.38 r90 top
RP801 "33R" RES_MNR04-8 2258.86,1750 r90 top
ST701 "2X1 2.54MM" HDR_M254-1X2 113.19,81.89 r90 top
SW1 "PTS810" SW_CK_PTS810_SJM_250 3922.91,1446.41 r90 top
SW100 "PTS810" SW_CK_PTS810_SJM_250 3887.8,352.27 r180 top
SW101 "PTS810" SW_CK_PTS810_SJM_250 3415.35,352.27 r180 top
SW704 "SW_DP3T" CK_DP3T_JS203011SCQN 822.83,181.1 r0 top
T1 "TOUCH SLIDER" TOUCH_SLIDER2_28.0X7.0-4 1228.35,389.76 r0 top
TAB1 "Comment" TAB_V-CUT_L7.0_W2.4 472.44,0.04 r180 top
TAB1_1 "Comment" TAB_V-CUT_L7.0_W2.4 472.44,0 r180 top
TAB2 "Comment" TAB_V-CUT_L7.0_W2.4 2362.2,0 r180 top
TAB2_1 "Comment" TAB_V-CUT_L7.0_W2.4 2362.2,0 r180 top
TAB3 "Comment" TAB_V-CUT_L7.0_W2.4 3858.27,0 r180 top
TAB3_1 "Comment" TAB_V-CUT_L7.0_W2.4 3858.27,0 r180 top
TAB4 "Comment" TAB_V-CUT_L7.0_W2.4 472.44,2362.2 r0 top
TAB4_1 "Comment" TAB_V-CUT_L7.0_W2.4 472.44,2362.2 r0 top
TAB5 "Comment" TAB_V-CUT_L7.0_W2.4 2362.2,2362.2 r0 top
TAB5_1 "Comment" TAB_V-CUT_L7.0_W2.4 2362.2,2362.2 r0 top
TAB6 "Comment" TAB_V-CUT_L7.0_W2.4 3858.27,2362.2 r0 top
TAB6_1 "Comment" TAB_V-CUT_L7.0_W2.4 3858.27,2362.2 r0 top
TP156 "TP_SMD" TP_1.0_SMD 602.36,181.1 r180 bottom
TP400 "TP_SMD" TP_1.0_SMD 3988.65,1322.8 r180 bottom
TP700 "TP_SMD" TP_1.0_SMD 1490.16,1159.45 r180 bottom
TP701 "TP_SMD" TP_1.0_SMD 1007.87,1455.71 r180 bottom
TP703 "TP_SMD" TP_1.0_SMD 1122.05,127.95 r180 bottom
TP705 "TP_SMD" TP_1.0_SMD 1643.7,1329.72 r180 bottom
TP706 "TP_SMD" TP_1.0_SMD 1291.34,1751.97 r180 bottom
TP707 "TP_SMD" TP_1.0_SMD 1586.61,1736.22 r180 bottom
TP708 "TP_SMD" TP_1.0_SMD 1018.7,931.1 r180 bottom
TP709 "TP_SMD" TP_1.0_SMD 930.12,164.37 r180 bottom
TP711 "TP_SMD" TP_1.0_SMD 1589.57,1262.8 r180 bottom
TP712 "TP_SMD" TP_1.0_SMD 1562.99,1354.33 r180 bottom
TP713 "TP_SMD" TP_1.0_SMD 1755.91,1299.21 r180 bottom
TP714 "TP_SMD" TP_1.0_SMD 1103.35,1182.78 r180 bottom
TP715 "TP_SMD" TP_1.0_SMD 1260.83,1222.44 r180 bottom
TP923 "TP_SMD" TP_1.0_SMD 1480.31,1439.96 r180 bottom
TP930 "TP_SMD" TP_1.0_SMD 2568.9,1153.54 r180 bottom
TPJ402 "TP_SMD" TP_1.0_SMD 3208.66,411.42 r180 bottom
TPJ403 "TP_SMD" TP_1.0_SMD 3041.35,411.39 r180 bottom
TPJ404 "TP_SMD" TP_1.0_SMD 2872.05,411.39 r180 bottom
TPJ405 "TP_SMD" TP_1.0_SMD 2917.35,245.99 r180 bottom
TPJ600 "TP_SMD" TP_1.0_SMD 564.95,1271.71 r180 bottom
TPJ606 "TP_SMD" TP_1.0_SMD 3834.65,1858.31 r180 bottom
TPJ607 "TP_SMD" TP_1.0_SMD 2624.02,1736.22 r180 bottom
TPJ608 "TP_SMD" TP_1.0_SMD 1359.25,808.11 r180 bottom
TPJ611 "TP_SMD" TP_1.0_SMD 399.55,2019.71 r180 bottom
TPJ612 "TP_SMD" TP_1.0_SMD 399.55,2120.11 r180 bottom
TPJ613 "TP_SMD" TP_1.0_SMD 499.95,2120.11 r180 bottom
TPJ614 "TP_SMD" TP_1.0_SMD 297.15,1960.61 r180 bottom
TPJ650 "TP_SMD" TP_1.0_SMD 4261.75,1702.81 r180 bottom
TPJ651 "TP_SMD" TP_1.0_SMD 4261.75,1563.01 r180 bottom
TPJ652 "TP_SMD" TP_1.0_SMD 2413.39,633.86 r180 bottom
TPJ653 "TP_SMD" TP_1.0_SMD 2045.28,633.86 r180 bottom
TPJ811 "TP_SMD" TP_1.0_SMD 3066.93,2074.8 r180 bottom
TPJ812 "TP_SMD" TP_1.0_SMD 3214.57,2104.33 r180 bottom
TPJ814 "TP_SMD" TP_1.0_SMD 3320.87,2137.8 r180 bottom
TPJ817 "TP_SMD" TP_1.0_SMD 4041.25,1903.51 r180 bottom
TPJ818 "TP_SMD" TP_1.0_SMD 2816.93,1612.2 r180 bottom
TPJ820 "TP_SMD" TP_1.0_SMD 3157.48,2005.91 r180 bottom
TPJ900 "TP_SMD" TP_1.0_SMD 1637.8,1492.13 r180 bottom
TPJ901 "TP_SMD" TP_1.0_SMD 1734.25,1517.72 r180 bottom
TPJ902 "TP_SMD" TP_1.0_SMD 968.5,1629.92 r180 bottom
TPJ908 "TP_SMD" TP_1.0_SMD 1730.31,1795.28 r180 bottom
TPJ909 "TP_SMD" TP_1.0_SMD 1679.13,1709.65 r180 bottom
TPJ910 "TP_SMD" TP_1.0_SMD 1889.76,1167.32 r180 bottom locked
TPJ911 "TP_SMD" TP_1.0_SMD 1789.37,1135.83 r180 bottom
TPJ912 "TP_SMD" TP_1.0_SMD 1998.03,1347.44 r180 bottom
TPJ913 "TP_SMD" TP_1.0_SMD 1998.03,1200.79 r180 bottom
TPJ950 "TP_SMD" TP_1.0_SMD 962.55,673.21 r180 bottom locked
TPJ953 "TP_SMD" TP_1.0_SMD 1653.54,994.09 r180 bottom
TPJ954 "TP_SMD" TP_1.0_SMD 1702.76,1082.68 r180 bottom
TPJ955 "TP_SMD" TP_1.0_SMD 1751.97,994.09 r180 bottom
TPJ956 "TP_SMD" TP_1.0_SMD 2076.77,1545.28 r180 bottom
TPJ957 "TP_SMD" TP_1.0_SMD 2039.33,1086.57 r180 bottom
TPJ958 "TP_SMD" TP_1.0_SMD 2092.52,1001.97 r180 bottom
TPJ959 "TP_SMD" TP_1.0_SMD 2145.63,1086.57 r180 bottom
TPJ960 "TP_SMD" TP_1.0_SMD 2122.01,1283.39 r90 bottom
TPJ961 "TP_SMD" TP_1.0_SMD 2124.02,1183.07 r180 bottom
U1 "EFM32LG990F256" BGA112_M080_10.0X10.0_SL 3370.08,1289.37 r0 top
U400 "AP2151" U-DFN2018-6_M050_2.0X1.8_EP 2849.88,306.14 r270 top
U600 "LP3982ILD-ADJ" WSON8_M050_3.0X2.5_EP_TI_NGM 920.73,1768.91 r90 top
U603 "TLV70536" DSBGA4_M040_0.8X0.8_TI_YFP 1512.8,1159.45 r180 top
U606 "MCP6001T" SC70-5 1647.64,1058.07 r180 top
U622 "MCP6001T" SC70-5 2010.83,1273.62 r180 top
U700 "SIP32431" TDFN4_M050_1.6X1.2_EP_VISH 1077.76,1171.26 r90 top
U701 "LP3982ILD-ADJ" WSON8_M050_3.0X2.5_EP_TI_NGM 1337.6,1098.43 r270 top
U702 "TS3A4751" QFN14_M040_2.0X2.0_TI_RUC 1447.84,1325.79 r180 top
U703 "LTC6102CDD" DFN8_M050_3.0X3.0_EP_LT_DD 1249.02,1429.13 r180 top
U704 "AD8656" MSOP8_M065_W3.0 1201.77,1614.17 r0 top
U800 "74LVC4066" DHVQFN14_M050_2.5X3_EP_NXP 2424.21,1751.97 r270 top
U802 "74LVC4066" DHVQFN14_M050_2.5X3_EP_NXP 2424.21,1574.8 r270 top
U803 "74LVC1T45" X2-DFN1010-6_M035_DIODES 2590.55,1629.92 r0 top
U804 "74LVC2G125" DSBGA8_M050_0.9X1.9_TI_YZP 1872.05,1395.67 r180 top
U805 "TS3A4751" QFN14_M040_2.0X2.0_TI_RUC 2183.07,1494.88 r90 top
U806 "74LVC4066" DHVQFN14_M050_2.5X3_EP_NXP 2424.21,1397.64 r270 top
U807 "74LVC1T45" X2-DFN1010-6_M035_DIODES 2599.6,1403.92 r0 top
U808 "74LVC8T245" VQFN24_M050_3.5X5.5_EP_TI_RHL 2128.94,1730.32 r0 top
U809 "74LVC2G125" DSBGA8_M050_0.9X1.9_TI_YZP 1873.03,1522.64 r180 top
U810 "74LVC4066" DHVQFN14_M050_2.5X3_EP_NXP 2424.21,1220.47 r270 top
U812 "TS3A4751" QFN14_M040_2.0X2.0_TI_RUC 2274.61,1218.5 r90 top
U860 "74LVC1T45" X2-DFN1010-6_M035_DIODES 1890.71,1772.01 r180 top
U861 "74LVC1T45" X2-DFN1010-6_M035_DIODES 2294.29,1606.3 r90 top
U862 "74LVC1T45" X2-DFN1010-6_M035_DIODES 2091.54,1539.37 r90 top
U863 "74LVC1T45" X2-DFN1010-6_M035_DIODES 2298.23,1366.14 r90 top
U900 "EFM32GG12B410F1024GL120-A" BGA120_M050_7.0X7.0_EFM32GGR 1680.12,1615.16 r180 top
U901 "M24C02" TDFN8_M050_2.0X3.0_EP 1882.87,1850.39 r0 top
U902 "MX25R8035F" BGA8_M040_1.24X1.75_WLCSP 1847.44,1271.65 r0 top
U910 "ADC084S021" VSSOP10_M050_W3.0_TI_DGS 1673.23,1260.83 r0 top
U950 "TS3A4751" QFN14_M040_2.0X2.0_TI_RUC 1937.01,1649.61 r270 top
X1 "48 MHz" X_KDS_DSX211SH_2.0X1.65-4 3453.74,1022.64 r180 top
X2 "32.768kHz" X_TAI-SAW-TZ2528C_2.05X1.2-2 3124.02,1148.62 r90 top
X900 "48 MHz" X_KDS_DSX211SH_2.0X1.65-4 1640.75,1822.83 r0 top
? "Comment" LOGO_EFM32_W18.0 2961.89,1751.97 r0 top locked

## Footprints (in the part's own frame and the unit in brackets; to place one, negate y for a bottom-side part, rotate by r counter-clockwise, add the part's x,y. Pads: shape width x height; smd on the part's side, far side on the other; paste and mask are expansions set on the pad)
BAT_HOLD_MPD_BK-912_CR2032 [mil] "MPD Battery Holder BK-912 (for CR2032)"
  rrect20% 110x200 smd: 1(-430,0) 1(430,0)
  round 157.48 smd paste-295.67 mask-82.68: 2(0,0)
  body extent -450,-394 450,394, height 171
BAT_SEIKO_XH311HG [mm] "Micro Battery Seiko XH311HG IV01E (Dia 3.8) (170308)"
  rrect20% 0.1x0.1 smd paste-0.1 mask-0.1: 1(1.7,-1.7)
  rrect20% 1x2.8 smd: 2(-1.6,-0.7)
  Top Layer region: 2.093,-2.04 2.093,-0.726 2.093,-0.715 2.082,-0.699 2.063,-0.691 2.043,-0.695 2.036,-0.702 2.036,-0.702 0.694,-2.044 0.687,-2.051 0.683,-2.071 0.69,-2.089 0.707,-2.1 0.717,-2.1 0.717,-2.1 2.033,-2.1 2.045,-2.1 2.067,-2.091 2.084,-2.074 2.093,-2.052 2.093,-2.04
  Top Layer keep-out region: -0.9,-2.1 0.4,-2.1 2,-0.5 2,0.641 2,0.775 1.948,1.038 1.845,1.285 1.697,1.508 1.508,1.697 1.285,1.845 1.038,1.948 0.775,2 0.641,2 0.641,2 -0.7,2 -0.808,2 -1.021,1.958 -1.221,1.875 -1.401,1.754 -1.554,1.601 -1.675,1.421 -1.758,1.221 -1.8,1.008 -1.8,0.9 -1.8,0.9 -0.9,0.9
  body extent -1.9,-1.9 1.9,1.9, height 1.1
BGA8_M040_1.24X1.75_WLCSP [mm] "BGA, 8 pin. U100"
  round 0.21 smd mask+0.05: A1(-0.35,0.4) A3(0.35,0.4) B2(0,0.2) C1(-0.35,0) C3(0.35,0) D2(0,-0.2) E1(-0.35,-0.4) E3(0.35,-0.4)
  body extent -0.63,-0.89 0.63,0.88, height 0.52
BGA112_M080_10.0X10.0_SL [mm] "BGA, 112-Leads, Body 10.0x10.0x1.3, Pitch 0,80 (190314)"
  round 0.35 smd: A1(-4,4) A2(-3.2,4) A3(-2.4,4) A4(-1.6,4) A5(-0.8,4) A6(0,4) A7(0.8,4) A8(1.6,4) A9(2.4,4) A10(3.2,4) A11(4,4) B1(-4,3.2) B2(-3.2,3.2) B3(-2.4,3.2) B4(-1.6,3.2) B5(-0.8,3.2) B6(0,3.2) B7(0.8,3.2) B8(1.6,3.2) B9(2.4,3.2) B10(3.2,3.2) B11(4,3.2) C1(-4,2.4) C2(-3.2,2.4) C3(-2.4,2.4) C4(-1.6,2.4) C5(-0.8,2.4) C6(0,2.4) C7(0.8,2.4) C8(1.6,2.4) C9(2.4,2.4) C10(3.2,2.4) C11(4,2.4) D1(-4,1.6) D2(-3.2,1.6) D3(-2.4,1.6) D4(-1.6,1.6) D5(-0.8,1.6) D6(0,1.6) D7(0.8,1.6) D8(1.6,1.6) D9(2.4,1.6) D10(3.2,1.6) D11(4,1.6) E1(-4,0.8) E2(-3.2,0.8) E3(-2.4,0.8) E4(-1.6,0.8) E8(1.6,0.8) E9(2.4,0.8) E10(3.2,0.8) E11(4,0.8) F1(-4,0) F2(-3.2,0) F3(-2.4,0) F4(-1.6,0) F8(1.6,0) F9(2.4,0) F10(3.2,0) F11(4,0) G1(-4,-0.8) G2(-3.2,-0.8) G3(-2.4,-0.8) G4(-1.6,-0.8) G8(1.6,-0.8) G9(2.4,-0.8) G10(3.2,-0.8) G11(4,-0.8) H1(-4,-1.6) H2(-3.2,-1.6) H3(-2.4,-1.6) H4(-1.6,-1.6) H5(-0.8,-1.6) H6(0,-1.6) H7(0.8,-1.6) H8(1.6,-1.6) H9(2.4,-1.6) H10(3.2,-1.6) H11(4,-1.6) J1(-4,-2.4) J2(-3.2,-2.4) J3(-2.4,-2.4) J4(-1.6,-2.4) J5(-0.8,-2.4) J6(0,-2.4) J7(0.8,-2.4) J8(1.6,-2.4) J9(2.4,-2.4) J10(3.2,-2.4) J11(4,-2.4) K1(-4,-3.2) K2(-3.2,-3.2) K3(-2.4,-3.2) K4(-1.6,-3.2) K5(-0.8,-3.2) K6(0,-3.2) K7(0.8,-3.2) K8(1.6,-3.2) K9(2.4,-3.2) K10(3.2,-3.2) K11(4,-3.2) L1(-4,-4) L2(-3.2,-4) L3(-2.4,-4) L4(-1.6,-4) L5(-0.8,-4) L6(0,-4) L7(0.8,-4) L8(1.6,-4) L9(2.4,-4) L10(3.2,-4) L11(4,-4)
  body extent -5,-5 5,5, height 1.3
BGA120_M050_7.0X7.0_EFM32GGR [mm] "BGA, 120 Leads, Body 7.0x7.0mmx1,30mm, Pitch 0.50mm (191111)"
  round 0.2 smd mask+0.04: A1(-3,3) A2(-2.5,3) A3(-2,3) A4(-1.5,3) A5(-1,3) A6(-0.5,3) A7(0,3) A8(0.5,3) A9(1,3) A10(1.5,3) A11(2,3) A12(2.5,3) A13(3,3) B1(-3,2.5) B2(-2.5,2.5) B3(-2,2.5) B4(-1.5,2.5) B5(-1,2.5) B6(-0.5,2.5) B7(0,2.5) B8(0.5,2.5) B9(1,2.5) B10(1.5,2.5) B11(2,2.5) B12(2.5,2.5) B13(3,2.5) C1(-3,2) C2(-2.5,2) C3(-2,2) C4(-1.5,2) C5(-1,2) C6(-0.5,2) C7(0,2) C8(0.5,2) C9(1,2) C10(1.5,2) C11(2,2) C12(2.5,2) C13(3,2) D1(-3,1.5) D2(-2.5,1.5) D3(-2,1.5) D11(2,1.5) D12(2.5,1.5) D13(3,1.5) E1(-3,1) E2(-2.5,1) E3(-2,1) E11(2,1) E12(2.5,1) E13(3,1) F1(-3,0.5) F2(-2.5,0.5) F3(-2,0.5) F11(2,0.5) F12(2.5,0.5) F13(3,0.5) G1(-3,0) G2(-2.5,0) G3(-2,0) G11(2,0) G12(2.5,0) G13(3,0) H1(-3,-0.5) H2(-2.5,-0.5) H3(-2,-0.5) H11(2,-0.5) H12(2.5,-0.5) H13(3,-0.5) J1(-3,-1) J2(-2.5,-1) J3(-2,-1) J11(2,-1) J12(2.5,-1) J13(3,-1) K1(-3,-1.5) K2(-2.5,-1.5) K3(-2,-1.5) K11(2,-1.5) K12(2.5,-1.5) K13(3,-1.5) L1(-3,-2) L2(-2.5,-2) L3(-2,-2) L4(-1.5,-2) L5(-1,-2) L6(-0.5,-2) L7(0,-2) L8(0.5,-2) L9(1,-2) L10(1.5,-2) L11(2,-2) L12(2.5,-2) L13(3,-2) M1(-3,-2.5) M2(-2.5,-2.5) M3(-2,-2.5) M4(-1.5,-2.5) M5(-1,-2.5) M6(-0.5,-2.5) M7(0,-2.5) M8(0.5,-2.5) M9(1,-2.5) M10(1.5,-2.5) M11(2,-2.5) M12(2.5,-2.5) M13(3,-2.5) N1(-3,-3) N2(-2.5,-3) N3(-2,-3) N4(-1.5,-3) N5(-1,-3) N6(-0.5,-3) N7(0,-3) N8(0.5,-3) N9(1,-3) N10(1.5,-3) N11(2,-3) N12(2.5,-3) N13(3,-3)
  body extent -3.5,-3.5 3.5,3.5, height 1.3
C0201 [mm] "Capacitor, 9291, HiDens (170502)"
  rrect25% 0.36x0.32 smd paste-0.015: 1(-0.275,0) 2(0.275,0)
  Top Layer pour cut-out: -0.075,-0.2 -0.075,0.2 0.075,0.2 0.075,-0.2
  body extent -0.32,-0.13 0.32,0.13, height 0.3
C0402 [mm] "Chip Capacitor, 2-Leads, Body 1.0x0.5mm, IPC High Density (190308)"
  rrect20% 0.5x0.5 smd mask+0.051: 1(-0.5,0) 2(0.5,0)
  Top Layer pour cut-out: -0.225,-0.3 -0.225,0.3 0.225,0.3 0.225,-0.3
  body extent -0.5,-0.25 0.5,0.25, height 0.6
C0603 [mm] "Capacitor, 0603, HiDens (190130)"
  rrect25% 0.8x0.85 smd: 1(-0.7,0) 2(0.7,0)
  Top Layer pour cut-out: -0.275,-0.55 -0.275,0.55 0.275,0.55 0.275,-0.55
  body extent -0.88,-0.48 0.87,0.48, height 0.95
CK_DP3T_JS203011SCQN [mm] "Switch, C & K DP3T JS203011SCQN (190314)"
  rrect50% 1.2x2.5 smd: 1(-4,-2.75) 2(-2,-2.75) 3(2,-2.75) 4(4,-2.75) 5(-4,2.75) 6(-2,2.75) 7(2,2.75) 8(4,2.75)
  body extent -6.5,-3.75 6.5,3.75, height 5.22
COIL_0402 [mm] "COIL_0402_L (3D from Wurth) (190308)"
  rrect20% 0.55x0.5 smd mask+0.051: 1(-0.525,0) 2(0.525,0)
  body extent -0.5,-0.25 0.5,0.25, height 0.5
COIL_BOURNS_SDR0302 [mm] "Coil Bourns SDR0302 D 3.0 H2.5 (190312)"
  rect 1.4x2 smd: 1(-1.1,0) 2(1.1,0)
  Top Layer region: -1.8,0.7 -1.8,1.175 -1.8,1.24 -1.751,1.359 -1.659,1.451 -1.54,1.5 -1.475,1.5 -1.475,1.5 -0.425,1.5 -0.42,1.5 -0.411,1.496 -0.404,1.489 -0.4,1.48 -0.4,1.475 -0.4,1.475 -0.4,0.7
  Top Layer region: 1.8,0.7 1.8,1.175 1.8,1.24 1.751,1.359 1.659,1.451 1.54,1.5 1.475,1.5 1.475,1.5 0.425,1.5 0.42,1.5 0.411,1.496 0.404,1.489 0.4,1.48 0.4,1.475 0.4,1.475 0.4,0.7
  Top Layer region: -1.8,-0.7 -1.8,-1.175 -1.8,-1.24 -1.751,-1.359 -1.659,-1.451 -1.54,-1.5 -1.475,-1.5 -1.475,-1.5 -0.425,-1.5 -0.42,-1.5 -0.411,-1.496 -0.404,-1.489 -0.4,-1.48 -0.4,-1.475 -0.4,-1.475 -0.4,-0.7
  Top Layer region: 1.8,-0.7 1.8,-1.175 1.8,-1.24 1.751,-1.359 1.659,-1.451 1.54,-1.5 1.475,-1.5 1.475,-1.5 0.425,-1.5 0.42,-1.5 0.411,-1.496 0.404,-1.489 0.4,-1.48 0.4,-1.475 0.4,-1.475 0.4,-0.7
  body extent -1.5,-1.5 1.5,1.5, height 2.8
COIL_WURTH_CBF_0603 [mm] "COIL_WURTH_CBF_0603 (= L0603_0.8_L) (181031)"
  rrect10% 0.67x0.88 smd: 1(-0.665,0) 2(0.665,0)
  body extent -0.87,-0.48 0.87,0.48, height 0.95
DFN8_M050_3.0X3.0_EP_LT_DD [mm] "DFN 8 Lead, Pitch 0.5, 3.0x3.0x0.75 Exposed Pad, Linear Tech (171004)"
  rrect50% 0.7x0.25 smd paste-0.025 mask+0.07: 1(-1.4,0.75) 2(-1.4,0.25) 3(-1.4,-0.25) 4(-1.4,-0.75) 5(1.4,-0.75) 6(1.4,-0.25) 7(1.4,0.25) 8(1.4,0.75)
  rect 1x1.8 smd paste-1 mask+0: 9(0,0)
  Top Layer region: 0.825,1.2 -0.693,1.2 -0.825,1.095 -0.825,-1.2 0.825,-1.2
  body extent -1.56,-1.55 1.56,1.55, height 0.8
DFN2111-7_M050_1.2X2.1_NXP [mm] "DFN2111-7 NXP Pitch 035 1.2x2.1x0.5, NXP (190312)"
  rrect20% 0.53x0.19 smd mask+0.05: 1(-0.415,0.75) 2(-0.415,0.25) 3(-0.415,-0.25) 4(-0.415,-0.75) 5(0.415,-0.5) 6(0.415,0) 7(0.415,0.5)
  body extent -0.6,-1.05 0.6,1.05, height 0.51
DHVQFN14_M050_2.5X3_EP_NXP [mm] "DHVQFN, 14 Leads, 2.5x3.0x0.85, Pitch 0.50, Thermal Pad 1.0x1.5 (190314)"
  oval 0.3x0.7 smd: 1(-0.25,1.45) 7(-0.25,-1.45) 8(0.25,-1.45) 14(0.25,1.45)
  oval 0.7x0.3 smd: 2(-1.2,1) 3(-1.2,0.5) 4(-1.2,0) 5(-1.2,-0.5) 6(-1.2,-1) 9(1.2,-1) 10(1.2,-0.5) 11(1.2,0) 12(1.2,0.5) 13(1.2,1)
  rrect10% 1x1.5 smd: 17(0,0)
  body extent -1.25,-1.5 1.25,1.5, height 1.1
DSBGA4_M040_0.8X0.8_TI_YFP [mm] "DS-BGA, 4 Leads, Body 0.8x0.8 H:0.5, Pitch 0.40"
  round 0.23 smd mask+0.04: A1(-0.2,0.2) A2(0.2,0.2) B1(-0.2,-0.2) B2(0.2,-0.2)
  body extent -0.4,-0.4 0.4,0.4, height 0.51
DSBGA8_M050_0.9X1.9_TI_YZP [mm] "DS-BGA, 8 Leads, Body 0.9x1.9 H:0.5, Pitch 0.50"
  round 0.23 smd: A1(-0.25,0.75) A2(0.25,0.75) B1(-0.25,0.25) B2(0.25,0.25) C1(-0.25,-0.25) C2(0.25,-0.25) D1(-0.25,-0.75) D2(0.25,-0.75)
  body extent -0.45,-0.95 0.45,0.95, height 0.51
FCI_10137065_USB-C_RCPT [mm] "FCI AMPHENOL 10137065 USB-C Receptacle (Slot PinInPaste) (180404)"
  oval 1.3x2.6 hole 0.7 slot 2 at 90 deg: 25(-4.32,-3.05) 26(4.32,-3.05)
  oval 1.3x2.6 on Top Paste: 25(-4.32,-3.05) 26(4.32,-3.05)
  oval 1.2x2.489 on Top Paste: 27(-4.32,2)
  oval 1.2x2.5 hole 0.6 slot 1.9 at 90 deg paste+0: 27(-4.32,2)
  oval 1.638x1.194 on Top Paste: 27(-4.025,1.35)
  oval 1.647x1.2 hole 0.6 slot 1.247 at 0 deg: 27(-4.025,1.35)
  oval 1.847x1.2 hole 0.6 slot 1.247 at 0 deg: 28(4.025,1.35)
  oval 1.841x1.194 on Top Paste: 28(4.025,1.35)
  oval 1.2x2.5 hole 0.6 slot 1.9 at 90 deg: 28(4.32,2)
  oval 1.194x2.489 on Top Paste: 28(4.32,2)
  rrect20% 0.27x0.9 smd mask+0.076: A1(-2.625,2.7) A2(-2.125,2.7) A3(-1.625,2.7) A4(-1.125,2.7) A5(-0.625,2.7) A6(-0.125,2.7) A7(0.375,2.7) A8(0.875,2.7) A9(1.375,2.7) A10(1.875,2.7) A11(2.375,2.7) A12(2.875,2.7)
  rrect20% 0.27x0.8 smd mask+0.076: B1(2.625,1.1) B2(2.125,1.1) B3(1.625,1.1) B4(1.125,1.1) B5(0.625,1.1) B6(0.125,1.1) B7(-0.375,1.1) B8(-0.875,1.1) B9(-1.375,1.1) B10(-1.875,1.1) B11(-2.375,1.1) B12(-2.875,1.1)
  round 0 hole 0.6 unplated mask+0.102: M1(-3.6,0)
  round 0 hole 0.5 slot 0.85 at 0 deg unplated mask+0.102: M2(3.6,0)
  Top Layer keep-out region: -3.9,-4.85 3.9,-4.85 3.9,0.4 -3.9,0.4
  body extent -4.47,-5.3 4.47,2.85, height 3.14
HDR_M254-1X2 [mm] "Connector; Header; 2 Position (170508)"
  round 1.6 hole 1: 1(0,0) 2(2.54,0)
  body extent -1.07,-1.17 3.61,1.17, height 8.12
HDR_M254_RING-2X16 [mm] "Connector; Header; 2x16 Position, 2.54mm (190312)"
  round 1.6 hole 1: 1(-19.05,-1.27) 2(-19.05,1.27) 3(-16.51,-1.27) 4(-16.51,1.27) 5(-13.97,-1.27) 6(-13.97,1.27) 7(-11.43,-1.27) 8(-11.43,1.27) 9(-8.89,-1.27) 10(-8.89,1.27) 11(-6.35,-1.27) 12(-6.35,1.27) 13(-3.81,-1.27) 14(-3.81,1.27) 15(-1.27,-1.27) 16(-1.27,1.27) 17(1.27,-1.27) 18(1.27,1.27) 19(3.81,-1.27) 20(3.81,1.27) 21(6.35,-1.27) 22(6.35,1.27) 23(8.89,-1.27) 24(8.89,1.27) 25(11.43,-1.27) 26(11.43,1.27) 27(13.97,-1.27) 28(13.97,1.27) 29(16.51,-1.27) 30(16.51,1.27) 31(19.05,-1.27) 32(19.05,1.27)
HDR_SULLINS_M127_PEG-2X10 [mil] "Sullins, GRPB102VQS (180319)"
  rrect50% 30x87 smd: 1(-25,-72.5) 2(-25,72.5) 3(25,-72.5) 4(25,72.5) 5(75,-72.5) 6(75,72.5) 7(125,-72.5) 8(125,72.5) 9(175,-72.5) 10(175,72.5) 11(225,-72.5) 12(225,72.5) 13(275,-72.5) 14(275,72.5) 15(325,-72.5) 16(325,72.5) 17(375,-72.5) 18(375,72.5) 19(425,-72.5) 20(425,72.5)
  round 0 hole 39.37 unplated mask+3.94: M1(0,0) M2(400,0)
  body extent -50,-100 450,101, height 197
HOLE_3.0_5.0_PL [mm] "Hole 3.0 mm, Plated (171122)"
  round 5 hole 3: 1(0,0)
HOLE_3.0_NPL [mm] "HOLE_3.0_NPL (170815)"
  round 0 hole 3 unplated mask+0.2: 1(0,0)
  body extent -1.5,-1.5 1.5,1.5
LABEL_4CORNERS_19.0X6.0 [mil]
  silkscreen extent -374,-118 374,118
LCD_TRI-T_CL010-1087-03 [mm] "LCD_TRI-T_CL010-1087-03 (190320)"
  round 1.4 hole 0.8: 1(-13,-12.7) 2(-11,-12.7) 3(-9,-12.7) 4(-7,-12.7) 5(-5,-12.7) 6(-3,-12.7) 7(-1,-12.7) 8(1,-12.7) 9(3,-12.7) 10(5,-12.7) 11(7,-12.7) 12(9,-12.7) 13(11,-12.7) 14(13,-12.7) 15(13,12.7) 16(11,12.7) 17(9,12.7) 18(7,12.7) 19(5,12.7) 20(3,12.7) 21(1,12.7) 22(-1,12.7) 23(-3,12.7) 24(-5,12.7) 25(-7,12.7) 26(-9,12.7) 27(-11,12.7) 28(-13,12.7)
LED_0402 [mm] "Chip Diode, 2-Leads, Body 1.00x0.50mm, IPC High Density (170127)"
  rrect10% 0.45x0.6 smd: 1(-0.45,0) 2(0.45,0)
  body extent -0.55,-0.33 0.55,0.33, height 0.25
LED_0402_CAT2 [mm] "(200921)"
  rrect10% 0.45x0.6 smd: 1(-0.45,0) 2(0.45,0)
  body extent -0.55,-0.33 0.55,0.33, height 0.25
LED_AVAGO_HSMF-C165-4 [mm] "LED (dual) Avago HSMF-C165 Grn+Red 1.6x0.8x0.5 (200226)"
  rrect20% 0.7x0.4 smd: 1(-0.65,-0.35) 2(-0.65,0.35) 3(0.65,0.35) 4(0.65,-0.35)
  body extent -0.8,-0.4 0.8,0.4, height 0.52
LOGO_EFM32_W18.0 [mil]
  silkscreen extent 488,3 712,91
LOGO_GECKO_H6.0 [mil] "Silicon Labs, Gecko logo"
  silkscreen extent 1,1 209,237
LOGO_SEGGER_10.0X5.0_SM [mil] "Logo, Segger 10.0x5.0, Top Solder + M19 + Top Overlay"
LOGO_SILABS_W18.0 [mil]
  silkscreen extent 1,1 669,328
MOL_47589-0001_MICRO_USB-AB [mm] "Molex 47589-0001 Micro USB Type AB (BOT) (190312)"
  rrect20% 0.4x1.35 smd mask+0.076: 1(-1.3,4.132) 2(-0.65,4.132) 3(0,4.132) 4(0.65,4.132) 5(1.3,4.132)
  oval 1.05x1.25 hole 0.65 slot 0.85 at 90 deg: 6(-2.217,4.454) 7(2.225,4.457)
  oval 1x1.9 hole 0.6 slot 1.3 at 90 deg paste+0: 8(-4.175,1.457) 9(4.175,1.457)
  rrect5% 1.8x1.9 smd: 10(-1.15,1.457) 11(1.15,1.457)
  Top Layer region: 4.251,0.514 2.669,0.514 2.657,0.514 2.635,0.523 2.618,0.54 2.608,0.562 2.608,0.574 2.608,0.574 2.597,2.329 2.597,2.343 2.608,2.37 2.628,2.39 2.655,2.401 2.67,2.401 2.67,2.401 4.163,2.401 4.265,2.401 4.454,2.323 4.598,2.179 4.676,1.991 4.676,1.889 4.676,1.889 4.676,0.939 4.677,0.911 4.668,0.855 4.649,0.801 4.62,0.753 4.6,0.732 4.57,0.689 4.492,0.616 4.402,0.56 4.303,0.523 4.251,0.514
  Top Layer region: -4.25,2.4 -2.668,2.4 -2.656,2.4 -2.634,2.391 -2.617,2.374 -2.607,2.352 -2.607,2.34 -2.607,2.34 -2.596,0.585 -2.596,0.571 -2.607,0.544 -2.627,0.524 -2.654,0.512 -2.669,0.513 -2.669,0.513 -4.163,0.512 -4.264,0.512 -4.453,0.59 -4.597,0.735 -4.675,0.923 -4.675,1.025 -4.675,1.025 -4.675,1.975 -4.676,2.003 -4.668,2.059 -4.648,2.113 -4.619,2.161 -4.6,2.182 -4.6,2.182 -4.569,2.225 -4.491,2.298 -4.401,2.354 -4.302,2.391 -4.25,2.4
  body extent -4.32,-1.3 4.32,4.59, height 2.71
MSOP8_M065_W3.0 [mm] "MSOP, 8-Leads, Body 3.0x3.0mm, Pitch 0.65mm (170921)"
  rrect20% 0.889x0.42 smd mask+0.048: 1(-2.105,0.975) 2(-2.105,0.325) 3(-2.105,-0.325) 4(-2.105,-0.975) 5(2.106,-0.975) 6(2.106,-0.325) 7(2.106,0.325) 8(2.106,0.975)
  body extent -1.55,-1.55 1.55,1.55, height 1.11
QFN14_M040_2.0X2.0_TI_RUC [mm] "QFN 14 Leads, Pitch 0.4 mm, 2.0 x 2.0 H: 0.37, TI: RUC (180613)"
  rrect20% 0.68x0.2 smd: 1(-0.885,0.8) 2(-0.885,0.4) 3(-0.885,0) 4(-0.885,-0.4) 5(-0.885,-0.8) 8(0.885,-0.8) 9(0.885,-0.4) 10(0.885,0) 11(0.885,0.4) 12(0.885,0.8)
  rrect20% 0.2x0.68 smd: 6(-0.2,-0.885) 7(0.2,-0.885) 13(0.2,0.885) 14(-0.2,0.885)
  body extent -1,-1 1,1, height 0.41
R0201 [mm] "Resistor (Chip2PinSM127P600-8N) (170921)"
  rrect25% 0.34x0.32 smd: 1(-0.3,0) 2(0.3,0)
  Top Layer pour cut-out: -0.1,-0.2 -0.1,0.2 0.1,0.2 0.1,-0.2
  body extent -0.32,-0.13 0.32,0.13, height 0.3
R0402 [mm] "Chip Resistor, 2-Leads, Body 1.0x0.5mm, HiDens (190308)"
  rrect20% 0.6x0.6 smd mask+0.051: 1(-0.45,0) 2(0.45,0)
  Top Layer pour cut-out: -0.125,-0.3 -0.125,0.3 0.125,0.3 0.125,-0.3
  body extent -0.5,-0.25 0.5,0.25, height 0.6
R0603 [mm] "Chip Resistor, 0603, HiDens (190130)"
  rrect25% 0.85x0.9 smd: 1(-0.7,0) 2(0.7,0)
  Top Layer pour cut-out: -0.25,-0.575 -0.25,0.575 0.25,0.575 0.25,-0.575
  body extent -0.88,-0.48 0.87,0.48, height 0.95
R1206 [mm] "Resistor, 1206, HiDens (191114)"
  rrect25% 0.85x1.65 smd paste-0.04 mask+0.07: 1(-1.425,0) 2(1.425,0)
  body extent -1.6,-0.8 1.6,0.8, height 1
RES_MNR04-8 [mm] "Resistor Array, ROHM MNR04 8-Pin 2.0x1.0x0.35 (!80615)"
  rrect20% 0.4x0.5 smd: 1(-0.75,-0.45) 4(0.75,-0.45) 5(0.75,0.45) 8(-0.75,0.45)
  rrect20% 0.3x0.5 smd: 2(-0.25,-0.45) 3(0.25,-0.45) 6(0.25,0.45) 7(-0.25,0.45)
  body extent -1,-0.4 1,0.4, height 0.5
SC70-5 [mm] "SC70-5 = SOT353, HiDens (170511)"
  rrect25% 0.6x0.4 smd paste-0.03 mask+0.05: 1(-0.95,0.65) 2(-0.95,0) 3(-0.95,-0.65) 4(0.95,-0.65) 5(0.95,0.65)
  body extent -1.12,-0.97 1.16,1.03, height 0.95
SOT563 [mm] "SOT563 (_M050_W1.2_), 6-Leads, Body 1.60x1.20, Pitch 0.5, HiDens (170926)"
  rrect25% 0.6x0.3 smd: 1(-0.65,0.5) 2(-0.65,0) 3(-0.65,-0.5) 4(0.65,-0.5) 5(0.65,0) 6(0.65,0.5)
  body extent -0.65,-0.85 0.65,0.85, height 0.6
SOT563_DIODES [mm] "SOT563 (_M050_W1.2_), 6-Leads, Body 1.60x1.20, Pitch 0.5, HiDens (170926)"
  rrect25% 0.5x0.375 smd: 1(-0.85,0.5) 2(-0.85,0) 3(-0.85,-0.5) 4(0.85,-0.5) 5(0.85,0) 6(0.85,0.5)
  body extent -0.66,-0.85 0.65,0.85, height 0.6
SW_CK_PTS810_SJM_250 [mm] "Switch C&K PTS810_SJM_250 (grey button) (180319)"
  rrect20% 1.05x0.65 smd: 1(-2.075,1.075) 2(2.075,1.075) 3(-2.075,-1.075) 4(2.075,-1.075)
  body extent -2.29,-1.6 2.29,1.6, height 2.5
TAB_V-CUT_L7.0_W2.4 [mil] "TAB V_CUT, Length 7.0, Width 2.4"
TDFN4_M050_1.6X1.2_EP_VISH [mm] "TDFN, 4-Leads, Body 1.60x1.20mm, IPC HiDens (180111)"
  rrect10% 0.55x0.3 smd: 1(-0.725,0.25) 2(-0.725,-0.25) 3(0.725,-0.25) 4(0.725,0.25)
  rrect10% 0.5x0.86 smd paste-0.05: 5(0,0)
  body extent -0.8,-0.6 0.8,0.6, height 0.61
TDFN8_M050_2.0X3.0_EP [mm] "TDFN8_M050_2.0x3.0_EP (170921)"
  rrect20% 0.75x0.3 smd: 1(-1.45,0.75) 2(-1.45,0.25) 3(-1.45,-0.25) 4(-1.45,-0.75) 5(1.45,-0.75) 6(1.45,-0.25) 7(1.45,0.25) 8(1.45,0.75)
  rrect10% 1.5x1.4 smd: 9(0,0)
  body extent -1.5,-1 1.5,1, height 1.01
TEMT6200FX01_GEN_0805 [mm] "Phototransistor, 0805"
  rrect25% 0.95x1.35 smd: 1(-0.8,0) 2(0.8,0)
  body extent -1.17,-0.77 1.15,0.77, height 1.45
TOUCH_SLIDER2_28.0X7.0-4 [mm] "TOUCH_SLIDER2_28.0X7.0-4 (170306)"
  round 1 smd paste-0.51 mask-0.51: 1(1.424,3.924) 2(11.4,4) 3(19.5,4) 4(27.6,4)
  Top Layer region: 7.4,7.5 1.6,7.5 0.5,7.5 0.5,4 0.5,0.5 1.6,0.5 7.4,0.5 7.4,0.7 1.9,2 7.7,3.9 7.7,4.1 1.938,6 7.4,7.3
  Top Layer region: 15.7,7.5 9.9,7.5 3.8,6 3.8,5.8 9.4,4 3.8,2.2 3.8,2 9.9,0.5 15.7,0.5 15.7,0.7 10.2,2 16,3.9 16,4.1 10.238,6 15.7,7.3
  Top Layer region: 24,7.5 18.2,7.5 12.1,6 12.1,5.8 17.7,4 12.1,2.2 12.1,2 18.2,0.5 24,0.5 24,0.7 18.5,2 24.3,3.9 24.3,4.1 18.538,6 24,7.3
  Top Layer region: 28.5,7.5 26.5,7.5 20.4,6 20.4,5.8 26,4 20.4,2.2 20.4,2 26.5,0.5 28.5,0.5 28.5,2
  silkscreen extent 1.32,0.82 27.68,7.2
TP_1.0_SMD [mm] "Test Point, 1.0 mm, SMD (170509)"
  round 1 smd paste-0.501: 1(0,0)
  body extent -0.5,-0.5 0.5,0.5, height 0.04
U-DFN2018-6_M050_2.0X1.8_EP [mm] "U-DFN2018-6, 6-Lead, 2.0x1.8x0.58. Exposed Pad (Diodes Inc)"
  rrect5% 0.35x0.25 smd mask+0.04: 1(-0.975,0.5) 2(-0.975,0) 3(-0.975,-0.5) 4(0.975,-0.5) 5(0.975,0) 6(0.975,0.5)
  rrect5% 1.2x1.6 smd mask+0.04: 7(0,0)
  body extent -0.9,-1 0.9,1, height 0.62
VQFN24_M050_3.5X5.5_EP_TI_RHL [mm] "VQFN 24 Leads, Pitch 0.50 3.5x5.0x0.9, TI: RHL (171011)"
  rrect20% 0.28x0.99 smd: 1(-0.75,2.795) 12(-0.75,-2.795) 13(0.75,-2.795) 24(0.75,2.795)
  rrect20% 0.99x0.28 smd: 2(-1.795,2.25) 3(-1.795,1.75) 4(-1.795,1.25) 5(-1.795,0.75) 6(-1.795,0.25) 7(-1.795,-0.25) 8(-1.795,-0.75) 9(-1.795,-1.25) 10(-1.795,-1.75) 11(-1.795,-2.25) 14(1.795,-2.25) 15(1.795,-1.75) 16(1.795,-1.25) 17(1.795,-0.75) 18(1.795,-0.25) 19(1.795,0.25) 20(1.795,0.75) 21(1.795,1.25) 22(1.795,1.75) 23(1.795,2.25)
  rrect5% 2.05x4.05 smd: 25(0,0)
  Top Layer region: 0.39,-3.26 0.39,-2 -0.39,-2 -0.39,-3.26 -0.39,-3.266 -0.385,-3.277 -0.377,-3.285 -0.366,-3.29 -0.36,-3.29 -0.36,-3.29 -0.14,-3.29 -0.134,-3.29 -0.123,-3.285 -0.115,-3.277 -0.11,-3.266 -0.11,-3.26 -0.11,-3.26 -0.11,-2.32 -0.11,-2.316 -0.107,-2.309 -0.101,-2.303 -0.094,-2.3 -0.09,-2.3 -0.09,-2.3 0.09,-2.3 0.094,-2.3 0.101,-2.303 0.107,-2.309 0.11,-2.316 0.11,-2.32 0.11,-2.32 0.11,-3.26 0.11,-3.266 0.115,-3.277 0.123,-3.285 0.134,-3.29 0.14,-3.29 0.14,-3.29 0.36,-3.29 0.366,-3.29 0.377,-3.285 0.385,-3.277 0.39,-3.266 0.39,-3.26
  Top Layer region: -0.39,3.26 -0.39,2 0.39,2 0.39,3.26 0.39,3.266 0.385,3.277 0.377,3.285 0.366,3.29 0.36,3.29 0.36,3.29 0.14,3.29 0.134,3.29 0.123,3.285 0.115,3.277 0.11,3.266 0.11,3.26 0.11,3.26 0.11,2.32 0.11,2.316 0.107,2.309 0.101,2.303 0.094,2.3 0.09,2.3 0.09,2.3 -0.09,2.3 -0.094,2.3 -0.101,2.303 -0.107,2.309 -0.11,2.316 -0.11,2.32 -0.11,2.32 -0.11,3.26 -0.11,3.266 -0.115,3.277 -0.123,3.285 -0.134,3.29 -0.14,3.29 -0.14,3.29 -0.36,3.29 -0.366,3.29 -0.377,3.285 -0.385,3.277 -0.39,3.266 -0.39,3.26
  body extent -1.75,-2.75 1.75,2.75, height 1
VSSOP10_M050_W3.0_TI_DGS [mm] "VSSOP, 10-Leads, 3.0x3.0x(max1.1), Pitch 0.50mm, (TI: DGS) (190816)"
  rrect20% 1.45x0.3 smd: 1(-2.2,1) 2(-2.2,0.5) 3(-2.2,0) 4(-2.2,-0.5) 5(-2.2,-1) 6(2.2,-1) 7(2.2,-0.5) 8(2.2,0) 9(2.2,0.5) 10(2.2,1)
  body extent -1.5,-1.5 1.5,1.5, height 1.1
WCON_1125B-1210_HOR_PEG-2X10 [mm] "WCON 2x10 header (201021)"
  rrect50% 1.27x3.175 smd: 1(-1.27,4.24) 2(-1.27,8.43) 3(1.27,4.24) 4(1.27,8.43) 5(3.81,4.24) 6(3.81,8.43) 7(6.35,4.24) 8(6.35,8.43) 9(8.89,4.24) 10(8.89,8.43) 11(11.43,4.24) 12(11.43,8.43) 13(13.97,4.24) 14(13.97,8.43) 15(16.51,4.24) 16(16.51,8.43) 17(19.05,4.24) 18(19.05,8.43) 19(21.59,4.24) 20(21.59,8.43)
  round 0 hole 1.9 unplated paste+0.91 mask+0.1: M1(0,0) M2(20.32,0)
  body extent -2.54,-7.11 22.86,9.15, height 6.1
WCON_3132_HDR_M127_SMD-2X10 [mm] "WCON_3132_HDR_M127_SMD-2X10 (210215)"
  rrect50% 0.74x2.4 smd: 1(-5.715,-1.95) 2(-5.715,1.95) 3(-4.445,-1.95) 4(-4.445,1.95) 5(-3.175,-1.95) 6(-3.175,1.95) 7(-1.905,-1.95) 8(-1.905,1.95) 9(-0.635,-1.95) 10(-0.635,1.95) 11(0.635,-1.95) 12(0.635,1.95) 13(1.905,-1.95) 14(1.905,1.95) 15(3.175,-1.95) 16(3.175,1.95) 17(4.445,-1.95) 18(4.445,1.95) 19(5.715,-1.95) 20(5.715,1.95)
  body extent -6.35,-4.53 6.35,2.84, height 6.58
WSON8_M050_3.0X2.5_EP_TI_NGM [mm] "WSON8, Pitch 0.5, 3.0x2.5x0.8 EP TI: NGM (181205)"
  rrect20% 0.5x0.25 smd mask+0.051: 1(-1.15,0.75) 2(-1.15,0.25) 3(-1.15,-0.25) 4(-1.15,-0.75) 5(1.15,-0.75) 6(1.15,-0.25) 7(1.15,0.25) 8(1.15,0.75)
  rrect10% 1.2x1.5 smd mask+0.051: 9(0,0)
  body extent -1.5,-1.25 1.5,1.25, height 0.8
X2-DFN1006-2 [mm] "Diodes case X2-DFN1006-2 part DESD5V0S1BLD (201012)"
  rrect20% 0.4x0.7 smd mask+0.04: 1(-0.35,0) 2(0.35,0)
  body extent -0.5,-0.3 0.5,0.3, height 0.41
X2-DFN1010-6_M035_DIODES [mm] "X2-DFN1010-6 Pitch 0.35 1.0x1.0x0.4, Diodes Inc (181025)"
  rrect20% 0.55x0.2 smd mask+0.04: 1(-0.35,0.35) 2(-0.35,0) 3(-0.35,-0.35) 4(0.35,-0.35) 5(0.35,0) 6(0.35,0.35)
  body extent -0.5,-0.5 0.5,0.5, height 0.41
X2-DFN2015-3_DIODES [mm] "X2-DFN2015-3 DIODES (181204)"
  rrect10% 0.5x0.31 smd mask+0.07: 1(-0.9,0.5) 2(-0.9,-0.5)
  rrect10% 0.75x0.31 smd mask+0.07: 3(0.775,0)
  Top Layer region: 0.5,0.55 0.5,-0.55 0.5,-0.57 0.485,-0.607 0.457,-0.635 0.42,-0.65 0.4,-0.65 0.4,-0.65 -0.4,-0.65 -0.42,-0.65 -0.457,-0.635 -0.485,-0.607 -0.5,-0.57 -0.5,-0.55 -0.5,-0.55 -0.5,0.55 -0.5,0.57 -0.485,0.607 -0.457,0.635 -0.42,0.65 -0.4,0.65 -0.4,0.65 0.4,0.65 0.42,0.65 0.457,0.635 0.485,0.607 0.5,0.57 0.5,0.55
  body extent -1.04,-0.79 1.04,0.79, height 0.4
X_KDS_DSX211SH_2.0X1.65-4 [mm] "X_KDS_DSX211SH_2.0X1.65-4 (190312)"
  rrect20% 0.9x0.8 smd: 1(-0.7,-0.55) 2(0.7,-0.55) 3(0.7,0.55) 4(-0.7,0.55)
  body extent -1.07,-0.87 1.07,0.87, height 0.5
X_TAI-SAW-TZ2528C_2.05X1.2-2 [mm]
  rrect50% 0.7x1.4 smd: 1(-0.75,0) 2(0.75,0)
  body extent -1,-0.6 1,0.6, height 0.6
